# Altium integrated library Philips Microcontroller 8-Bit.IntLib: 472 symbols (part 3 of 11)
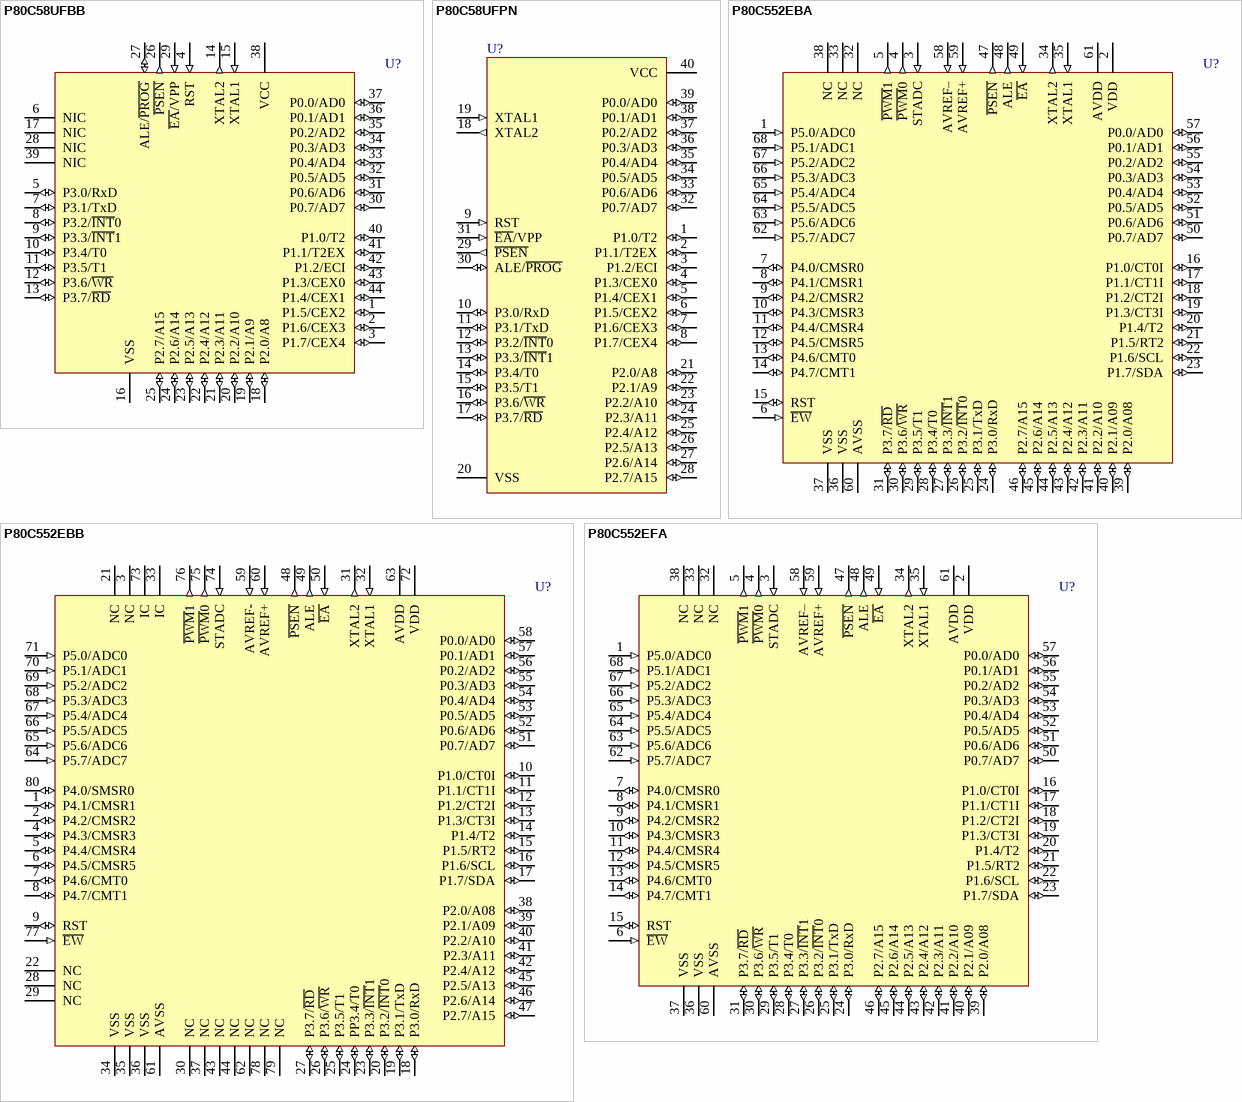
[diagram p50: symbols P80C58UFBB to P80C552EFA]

## P80C552EFA
designator U?
ROMless, Single-Chip 8-Bit Microcontroller with 10-bit A/D, Capture/Compare Timer, High-Speed Outputs, PWM
footprint SOT188-2_N (Leaded Chip Carrier, 68-Leads, Body 24.2x24.2mm, Pitch 1.27mm, IPC Medium Density)
footprint SOT188-2_L (Leaded Chip Carrier, 68-Leads, Body 24.2x24.2mm, Pitch 1.27mm, IPC High Density)
footprint SOT188-2_M (Leaded Chip Carrier, 68-Leads, Body 24.2x24.2mm, Pitch 1.27mm, IPC Low Density)
pins: 1 P5.0/ADC0 (in), 2 VDD (power), 3 STADC (in), 4 ~{PWM}0 (out), 5 ~{PWM}1 (out), 6 ~{EW} (in), 7 P4.0/CMSR0 (io), 8 P4.1/CMSR1 (io), 9 P4.2/CMSR2 (io), 10 P4.3/CMSR3 (io), 11 P4.4/CMSR4 (io), 12 P4.5/CMSR5 (io), 13 P4.6/CMT0 (io), 14 P4.7/CMT1 (io), 15 RST (io), 16 P1.0/CT0I (io), 17 P1.1/CT1I (io), 18 P1.2/CT2I (io), 19 P1.3/CT3I (io), 20 P1.4/T2 (io), 21 P1.5/RT2 (io), 22 P1.6/SCL (io), 23 P1.7/SDA (io), 24 P3.0/RxD (io), 25 P3.1/TxD (io), 26 P3.2/~{INT}0 (io), 27 P3.3/~{INT}1 (io), 28 P3.4/T0 (io), 29 P3.5/T1 (io), 30 P3.6/~{WR} (io), 31 P3.7/~{RD} (io), 32 NC, 33 NC, 34 XTAL2 (out), 35 XTAL1 (in), 36 VSS (power), 37 VSS (power), 38 NC, 39 P2.0/A08 (io), 40 P2.1/A09 (io), 41 P2.2/A10 (io), 42 P2.3/A11 (io), 43 P2.4/A12 (io), 44 P2.5/A13 (io), 45 P2.6/A14 (io), 46 P2.7/A15 (io), 47 ~{PSEN} (out), 48 ALE (out), 49 ~{EA} (in), 50 P0.7/AD7 (io), 51 P0.6/AD6 (io), 52 P0.5/AD5 (io), 53 P0.4/AD4 (io), 54 P0.3/AD3 (io), 55 P0.2/AD2 (io), 56 P0.1/AD1 (io), 57 P0.0/AD0 (io), 58 AVREF– (in), 59 AVREF+ (in), 60 AVSS (power), 61 AVDD (power), 62 P5.7/ADC7 (in), 63 P5.6/ADC6 (in), 64 P5.5/ADC5 (in), 65 P5.4/ADC4 (in), 66 P5.3/ADC3 (in), 67 P5.2/ADC2 (in), 68 P5.1/ADC1 (in)

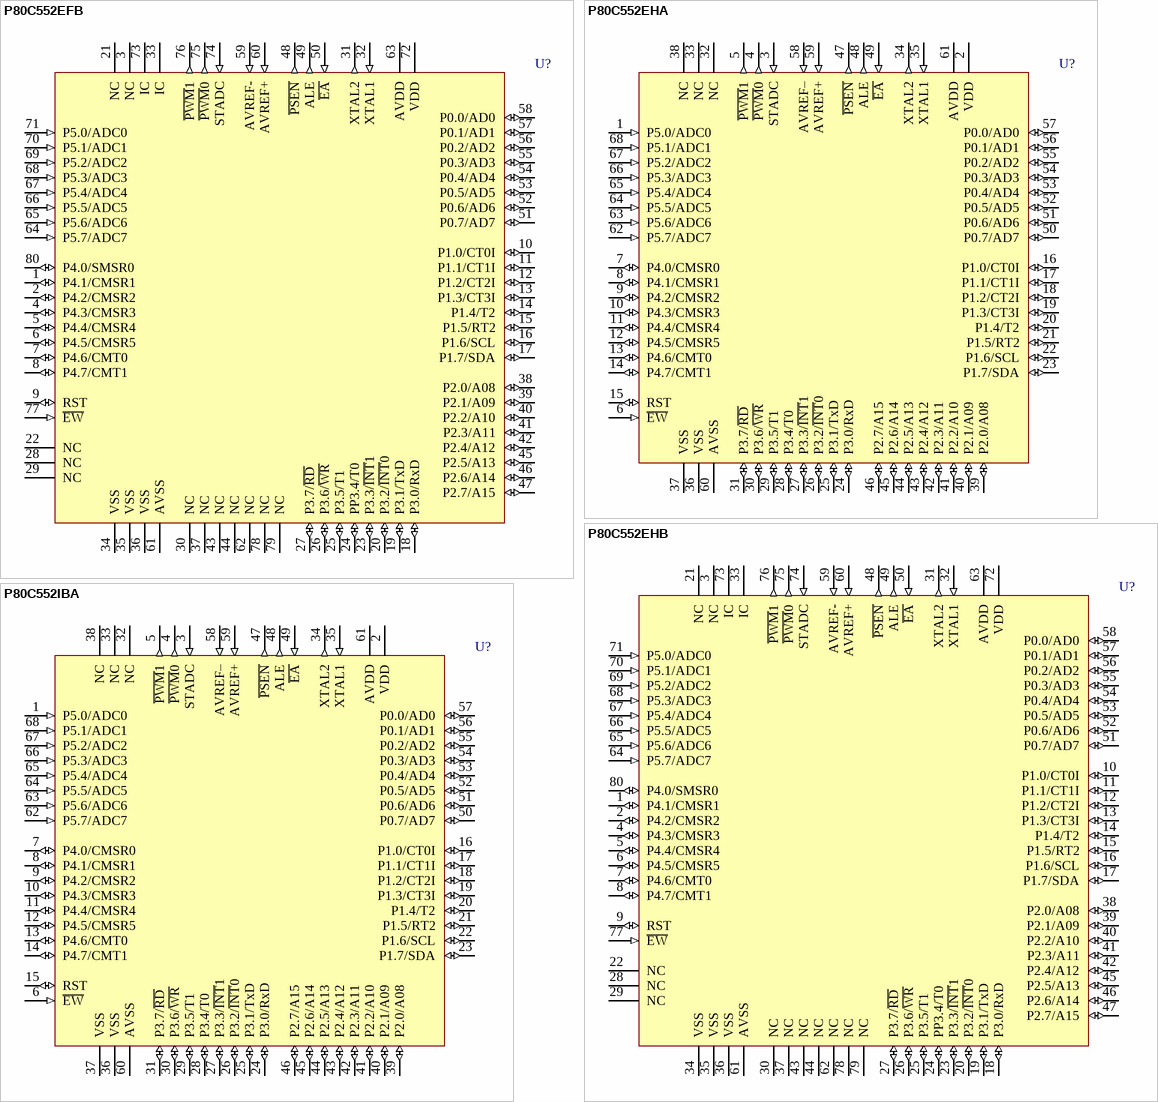
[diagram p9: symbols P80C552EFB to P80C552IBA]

## P80C552EFB
designator U?
ROMless, Single-Chip 8-Bit Microcontroller with 10-bit A/D, Capture/Compare Timer, High-Speed Outputs, PWM; DoNotConnect: Pins 33 & 73 are internally connected (IC), do not use.
footprint SOT318-2_N (QFP, 80-Leads, Body 20x14mm, Pitch 0.8mm, IPC Medium Density)
footprint SOT318-2_L (QFP, 80-Leads, Body 20x14mm, Pitch 0.8mm, IPC High Density)
footprint SOT318-2_M (QFP, 80-Leads, Body 20x14mm, Pitch 0.8mm, IPC Low Density)
pins: 1 P4.1/CMSR1 (io), 2 P4.2/CMSR2 (io), 3 NC, 4 P4.3/CMSR3 (io), 5 P4.4/CMSR4 (io), 6 P4.5/CMSR5 (io), 7 P4.6/CMT0 (io), 8 P4.7/CMT1 (io), 9 RST (io), 10 P1.0/CT0I (io), 11 P1.1/CT1I (io), 12 P1.2/CT2I (io), 13 P1.3/CT3I (io), 14 P1.4/T2 (io), 15 P1.5/RT2 (io), 16 P1.6/SCL (io), 17 P1.7/SDA (io), 18 P3.0/RxD (io), 19 P3.1/TxD (io), 20 P3.2/~{INT}0 (io), 21 NC, 22 NC, 23 P3.3/~{INT}1 (io), 24 PP3.4/T0 (io), 25 P3.5/T1 (io), 26 P3.6/~{WR} (io), 27 P3.7/~{RD} (io), 28 NC, 29 NC, 30 NC, 31 XTAL2 (out), 32 XTAL1 (in), 33 IC, 34 VSS (power), 35 VSS (power), 36 VSS (power), 37 NC, 38 P2.0/A08 (io), 39 P2.1/A09 (io), 40 P2.2/A10 (io), 41 P2.3/A11 (io), 42 P2.4/A12 (io), 43 NC, 44 NC, 45 P2.5/A13 (io), 46 P2.6/A14 (io), 47 P2.7/A15 (io), 48 ~{PSEN} (out), 49 ALE (out), 50 ~{EA} (in), 51 P0.7/AD7 (io), 52 P0.6/AD6 (io), 53 P0.5/AD5 (io), 54 P0.4/AD4 (io), 55 P0.3/AD3 (io), 56 P0.2/AD2 (io), 57 P0.1/AD1 (io), 58 P0.0/AD0 (io), 59 AVREF- (in), 60 AVREF+ (in), 61 AVSS (power), 62 NC, 63 AVDD (power), 64 P5.7/ADC7 (in), 65 P5.6/ADC6 (in), 66 P5.5/ADC5 (in), 67 P5.4/ADC4 (in), 68 P5.3/ADC3 (in), 69 P5.2/ADC2 (in), 70 P5.1/ADC1 (in), 71 P5.0/ADC0 (in), 72 VDD (power), 73 IC, 74 STADC (in), 75 ~{PWM}0 (out), 76 ~{PWM}1 (out), 77 ~{EW} (in), 78 NC, 79 NC, 80 P4.0/SMSR0 (io)

## P80C552EHA
designator U?
ROMless, Single-Chip 8-Bit Microcontroller with 10-bit A/D, Capture/Compare Timer, High-Speed Outputs, PWM
footprint SOT188-2_N (Leaded Chip Carrier, 68-Leads, Body 24.2x24.2mm, Pitch 1.27mm, IPC Medium Density)
footprint SOT188-2_L (Leaded Chip Carrier, 68-Leads, Body 24.2x24.2mm, Pitch 1.27mm, IPC High Density)
footprint SOT188-2_M (Leaded Chip Carrier, 68-Leads, Body 24.2x24.2mm, Pitch 1.27mm, IPC Low Density)
pins: 1 P5.0/ADC0 (in), 2 VDD (power), 3 STADC (in), 4 ~{PWM}0 (out), 5 ~{PWM}1 (out), 6 ~{EW} (in), 7 P4.0/CMSR0 (io), 8 P4.1/CMSR1 (io), 9 P4.2/CMSR2 (io), 10 P4.3/CMSR3 (io), 11 P4.4/CMSR4 (io), 12 P4.5/CMSR5 (io), 13 P4.6/CMT0 (io), 14 P4.7/CMT1 (io), 15 RST (io), 16 P1.0/CT0I (io), 17 P1.1/CT1I (io), 18 P1.2/CT2I (io), 19 P1.3/CT3I (io), 20 P1.4/T2 (io), 21 P1.5/RT2 (io), 22 P1.6/SCL (io), 23 P1.7/SDA (io), 24 P3.0/RxD (io), 25 P3.1/TxD (io), 26 P3.2/~{INT}0 (io), 27 P3.3/~{INT}1 (io), 28 P3.4/T0 (io), 29 P3.5/T1 (io), 30 P3.6/~{WR} (io), 31 P3.7/~{RD} (io), 32 NC, 33 NC, 34 XTAL2 (out), 35 XTAL1 (in), 36 VSS (power), 37 VSS (power), 38 NC, 39 P2.0/A08 (io), 40 P2.1/A09 (io), 41 P2.2/A10 (io), 42 P2.3/A11 (io), 43 P2.4/A12 (io), 44 P2.5/A13 (io), 45 P2.6/A14 (io), 46 P2.7/A15 (io), 47 ~{PSEN} (out), 48 ALE (out), 49 ~{EA} (in), 50 P0.7/AD7 (io), 51 P0.6/AD6 (io), 52 P0.5/AD5 (io), 53 P0.4/AD4 (io), 54 P0.3/AD3 (io), 55 P0.2/AD2 (io), 56 P0.1/AD1 (io), 57 P0.0/AD0 (io), 58 AVREF– (in), 59 AVREF+ (in), 60 AVSS (power), 61 AVDD (power), 62 P5.7/ADC7 (in), 63 P5.6/ADC6 (in), 64 P5.5/ADC5 (in), 65 P5.4/ADC4 (in), 66 P5.3/ADC3 (in), 67 P5.2/ADC2 (in), 68 P5.1/ADC1 (in)

## P80C552EHB
designator U?
ROMless, Single-Chip 8-Bit Microcontroller with 10-bit A/D, Capture/Compare Timer, High-Speed Outputs, PWM; DoNotConnect: Pins 33 & 73 are internally connected (IC), do not use.
footprint SOT318-2_N (QFP, 80-Leads, Body 20x14mm, Pitch 0.8mm, IPC Medium Density)
footprint SOT318-2_L (QFP, 80-Leads, Body 20x14mm, Pitch 0.8mm, IPC High Density)
footprint SOT318-2_M (QFP, 80-Leads, Body 20x14mm, Pitch 0.8mm, IPC Low Density)
pins: 1 P4.1/CMSR1 (io), 2 P4.2/CMSR2 (io), 3 NC, 4 P4.3/CMSR3 (io), 5 P4.4/CMSR4 (io), 6 P4.5/CMSR5 (io), 7 P4.6/CMT0 (io), 8 P4.7/CMT1 (io), 9 RST (io), 10 P1.0/CT0I (io), 11 P1.1/CT1I (io), 12 P1.2/CT2I (io), 13 P1.3/CT3I (io), 14 P1.4/T2 (io), 15 P1.5/RT2 (io), 16 P1.6/SCL (io), 17 P1.7/SDA (io), 18 P3.0/RxD (io), 19 P3.1/TxD (io), 20 P3.2/~{INT}0 (io), 21 NC, 22 NC, 23 P3.3/~{INT}1 (io), 24 PP3.4/T0 (io), 25 P3.5/T1 (io), 26 P3.6/~{WR} (io), 27 P3.7/~{RD} (io), 28 NC, 29 NC, 30 NC, 31 XTAL2 (out), 32 XTAL1 (in), 33 IC, 34 VSS (power), 35 VSS (power), 36 VSS (power), 37 NC, 38 P2.0/A08 (io), 39 P2.1/A09 (io), 40 P2.2/A10 (io), 41 P2.3/A11 (io), 42 P2.4/A12 (io), 43 NC, 44 NC, 45 P2.5/A13 (io), 46 P2.6/A14 (io), 47 P2.7/A15 (io), 48 ~{PSEN} (out), 49 ALE (out), 50 ~{EA} (in), 51 P0.7/AD7 (io), 52 P0.6/AD6 (io), 53 P0.5/AD5 (io), 54 P0.4/AD4 (io), 55 P0.3/AD3 (io), 56 P0.2/AD2 (io), 57 P0.1/AD1 (io), 58 P0.0/AD0 (io), 59 AVREF- (in), 60 AVREF+ (in), 61 AVSS (power), 62 NC, 63 AVDD (power), 64 P5.7/ADC7 (in), 65 P5.6/ADC6 (in), 66 P5.5/ADC5 (in), 67 P5.4/ADC4 (in), 68 P5.3/ADC3 (in), 69 P5.2/ADC2 (in), 70 P5.1/ADC1 (in), 71 P5.0/ADC0 (in), 72 VDD (power), 73 IC, 74 STADC (in), 75 ~{PWM}0 (out), 76 ~{PWM}1 (out), 77 ~{EW} (in), 78 NC, 79 NC, 80 P4.0/SMSR0 (io)

## P80C552IBA
designator U?
ROMless, Single-Chip 8-Bit Microcontroller with 10-bit A/D, Capture/Compare Timer, High-Speed Outputs, PWM
footprint SOT188-2_N (Leaded Chip Carrier, 68-Leads, Body 24.2x24.2mm, Pitch 1.27mm, IPC Medium Density)
footprint SOT188-2_L (Leaded Chip Carrier, 68-Leads, Body 24.2x24.2mm, Pitch 1.27mm, IPC High Density)
footprint SOT188-2_M (Leaded Chip Carrier, 68-Leads, Body 24.2x24.2mm, Pitch 1.27mm, IPC Low Density)
pins: 1 P5.0/ADC0 (in), 2 VDD (power), 3 STADC (in), 4 ~{PWM}0 (out), 5 ~{PWM}1 (out), 6 ~{EW} (in), 7 P4.0/CMSR0 (io), 8 P4.1/CMSR1 (io), 9 P4.2/CMSR2 (io), 10 P4.3/CMSR3 (io), 11 P4.4/CMSR4 (io), 12 P4.5/CMSR5 (io), 13 P4.6/CMT0 (io), 14 P4.7/CMT1 (io), 15 RST (io), 16 P1.0/CT0I (io), 17 P1.1/CT1I (io), 18 P1.2/CT2I (io), 19 P1.3/CT3I (io), 20 P1.4/T2 (io), 21 P1.5/RT2 (io), 22 P1.6/SCL (io), 23 P1.7/SDA (io), 24 P3.0/RxD (io), 25 P3.1/TxD (io), 26 P3.2/~{INT}0 (io), 27 P3.3/~{INT}1 (io), 28 P3.4/T0 (io), 29 P3.5/T1 (io), 30 P3.6/~{WR} (io), 31 P3.7/~{RD} (io), 32 NC, 33 NC, 34 XTAL2 (out), 35 XTAL1 (in), 36 VSS (power), 37 VSS (power), 38 NC, 39 P2.0/A08 (io), 40 P2.1/A09 (io), 41 P2.2/A10 (io), 42 P2.3/A11 (io), 43 P2.4/A12 (io), 44 P2.5/A13 (io), 45 P2.6/A14 (io), 46 P2.7/A15 (io), 47 ~{PSEN} (out), 48 ALE (out), 49 ~{EA} (in), 50 P0.7/AD7 (io), 51 P0.6/AD6 (io), 52 P0.5/AD5 (io), 53 P0.4/AD4 (io), 54 P0.3/AD3 (io), 55 P0.2/AD2 (io), 56 P0.1/AD1 (io), 57 P0.0/AD0 (io), 58 AVREF– (in), 59 AVREF+ (in), 60 AVSS (power), 61 AVDD (power), 62 P5.7/ADC7 (in), 63 P5.6/ADC6 (in), 64 P5.5/ADC5 (in), 65 P5.4/ADC4 (in), 66 P5.3/ADC3 (in), 67 P5.2/ADC2 (in), 68 P5.1/ADC1 (in)

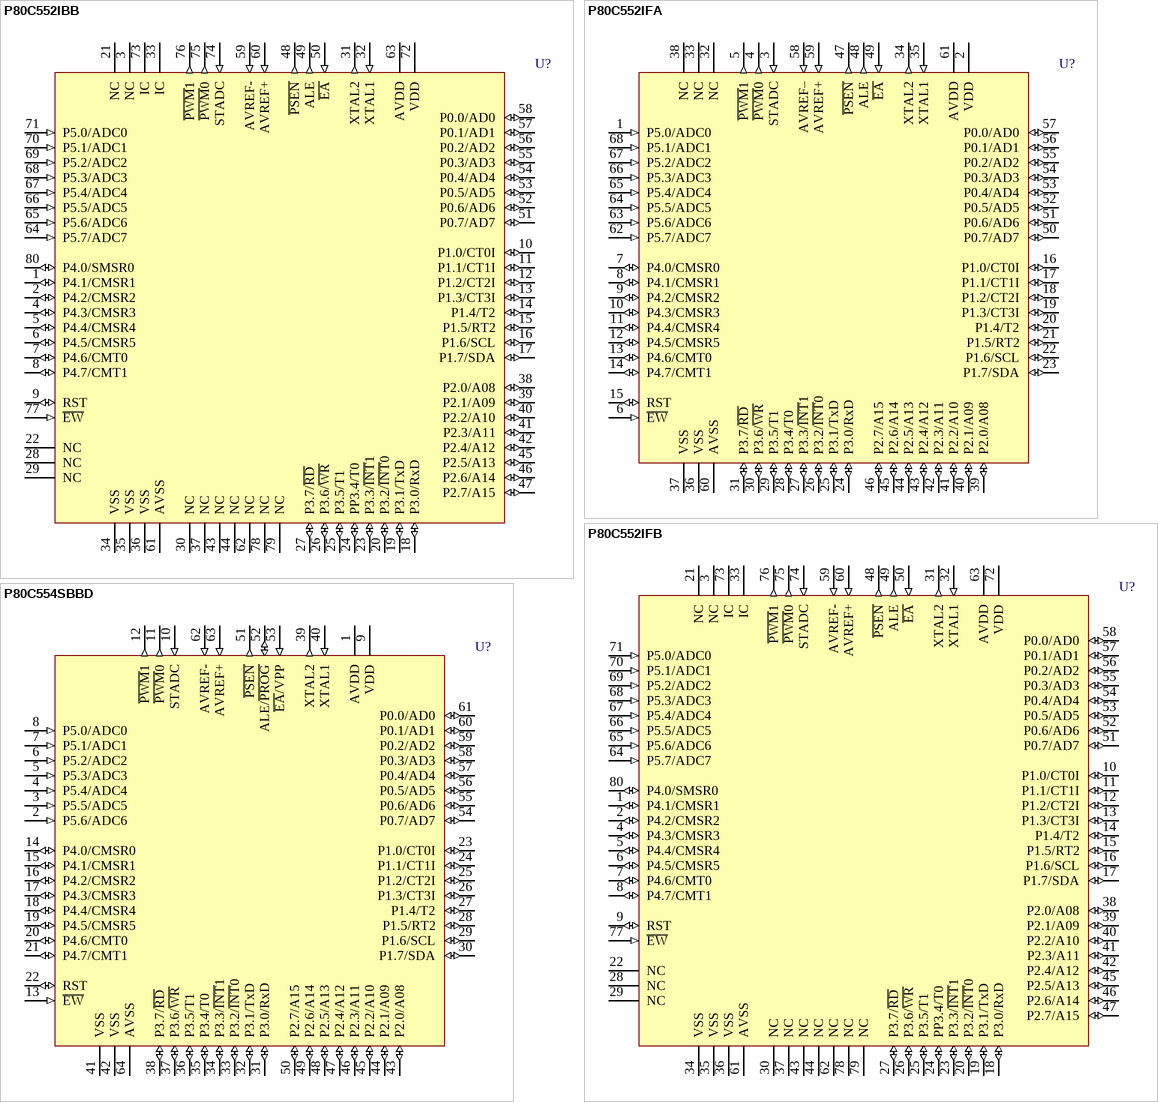
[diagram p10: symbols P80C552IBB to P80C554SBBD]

## P80C552IBB
designator U?
ROMless, Single-Chip 8-Bit Microcontroller with 10-bit A/D, Capture/Compare Timer, High-Speed Outputs, PWM; DoNotConnect: Pins 33 & 73 are internally connected (IC), do not use.
footprint SOT318-2_N (QFP, 80-Leads, Body 20x14mm, Pitch 0.8mm, IPC Medium Density)
footprint SOT318-2_L (QFP, 80-Leads, Body 20x14mm, Pitch 0.8mm, IPC High Density)
footprint SOT318-2_M (QFP, 80-Leads, Body 20x14mm, Pitch 0.8mm, IPC Low Density)
pins: 1 P4.1/CMSR1 (io), 2 P4.2/CMSR2 (io), 3 NC, 4 P4.3/CMSR3 (io), 5 P4.4/CMSR4 (io), 6 P4.5/CMSR5 (io), 7 P4.6/CMT0 (io), 8 P4.7/CMT1 (io), 9 RST (io), 10 P1.0/CT0I (io), 11 P1.1/CT1I (io), 12 P1.2/CT2I (io), 13 P1.3/CT3I (io), 14 P1.4/T2 (io), 15 P1.5/RT2 (io), 16 P1.6/SCL (io), 17 P1.7/SDA (io), 18 P3.0/RxD (io), 19 P3.1/TxD (io), 20 P3.2/~{INT}0 (io), 21 NC, 22 NC, 23 P3.3/~{INT}1 (io), 24 PP3.4/T0 (io), 25 P3.5/T1 (io), 26 P3.6/~{WR} (io), 27 P3.7/~{RD} (io), 28 NC, 29 NC, 30 NC, 31 XTAL2 (out), 32 XTAL1 (in), 33 IC, 34 VSS (power), 35 VSS (power), 36 VSS (power), 37 NC, 38 P2.0/A08 (io), 39 P2.1/A09 (io), 40 P2.2/A10 (io), 41 P2.3/A11 (io), 42 P2.4/A12 (io), 43 NC, 44 NC, 45 P2.5/A13 (io), 46 P2.6/A14 (io), 47 P2.7/A15 (io), 48 ~{PSEN} (out), 49 ALE (out), 50 ~{EA} (in), 51 P0.7/AD7 (io), 52 P0.6/AD6 (io), 53 P0.5/AD5 (io), 54 P0.4/AD4 (io), 55 P0.3/AD3 (io), 56 P0.2/AD2 (io), 57 P0.1/AD1 (io), 58 P0.0/AD0 (io), 59 AVREF- (in), 60 AVREF+ (in), 61 AVSS (power), 62 NC, 63 AVDD (power), 64 P5.7/ADC7 (in), 65 P5.6/ADC6 (in), 66 P5.5/ADC5 (in), 67 P5.4/ADC4 (in), 68 P5.3/ADC3 (in), 69 P5.2/ADC2 (in), 70 P5.1/ADC1 (in), 71 P5.0/ADC0 (in), 72 VDD (power), 73 IC, 74 STADC (in), 75 ~{PWM}0 (out), 76 ~{PWM}1 (out), 77 ~{EW} (in), 78 NC, 79 NC, 80 P4.0/SMSR0 (io)

## P80C552IFA
designator U?
ROMless, Single-Chip 8-Bit Microcontroller with 10-bit A/D, Capture/Compare Timer, High-Speed Outputs, PWM
footprint SOT188-2_N (Leaded Chip Carrier, 68-Leads, Body 24.2x24.2mm, Pitch 1.27mm, IPC Medium Density)
footprint SOT188-2_L (Leaded Chip Carrier, 68-Leads, Body 24.2x24.2mm, Pitch 1.27mm, IPC High Density)
footprint SOT188-2_M (Leaded Chip Carrier, 68-Leads, Body 24.2x24.2mm, Pitch 1.27mm, IPC Low Density)
pins: 1 P5.0/ADC0 (in), 2 VDD (power), 3 STADC (in), 4 ~{PWM}0 (out), 5 ~{PWM}1 (out), 6 ~{EW} (in), 7 P4.0/CMSR0 (io), 8 P4.1/CMSR1 (io), 9 P4.2/CMSR2 (io), 10 P4.3/CMSR3 (io), 11 P4.4/CMSR4 (io), 12 P4.5/CMSR5 (io), 13 P4.6/CMT0 (io), 14 P4.7/CMT1 (io), 15 RST (io), 16 P1.0/CT0I (io), 17 P1.1/CT1I (io), 18 P1.2/CT2I (io), 19 P1.3/CT3I (io), 20 P1.4/T2 (io), 21 P1.5/RT2 (io), 22 P1.6/SCL (io), 23 P1.7/SDA (io), 24 P3.0/RxD (io), 25 P3.1/TxD (io), 26 P3.2/~{INT}0 (io), 27 P3.3/~{INT}1 (io), 28 P3.4/T0 (io), 29 P3.5/T1 (io), 30 P3.6/~{WR} (io), 31 P3.7/~{RD} (io), 32 NC, 33 NC, 34 XTAL2 (out), 35 XTAL1 (in), 36 VSS (power), 37 VSS (power), 38 NC, 39 P2.0/A08 (io), 40 P2.1/A09 (io), 41 P2.2/A10 (io), 42 P2.3/A11 (io), 43 P2.4/A12 (io), 44 P2.5/A13 (io), 45 P2.6/A14 (io), 46 P2.7/A15 (io), 47 ~{PSEN} (out), 48 ALE (out), 49 ~{EA} (in), 50 P0.7/AD7 (io), 51 P0.6/AD6 (io), 52 P0.5/AD5 (io), 53 P0.4/AD4 (io), 54 P0.3/AD3 (io), 55 P0.2/AD2 (io), 56 P0.1/AD1 (io), 57 P0.0/AD0 (io), 58 AVREF– (in), 59 AVREF+ (in), 60 AVSS (power), 61 AVDD (power), 62 P5.7/ADC7 (in), 63 P5.6/ADC6 (in), 64 P5.5/ADC5 (in), 65 P5.4/ADC4 (in), 66 P5.3/ADC3 (in), 67 P5.2/ADC2 (in), 68 P5.1/ADC1 (in)

## P80C552IFB
designator U?
ROMless, Single-Chip 8-Bit Microcontroller with 10-bit A/D, Capture/Compare Timer, High-Speed Outputs, PWM; DoNotConnect: Pins 33 & 73 are internally connected (IC), do not use.
footprint SOT318-2_N (QFP, 80-Leads, Body 20x14mm, Pitch 0.8mm, IPC Medium Density)
footprint SOT318-2_L (QFP, 80-Leads, Body 20x14mm, Pitch 0.8mm, IPC High Density)
footprint SOT318-2_M (QFP, 80-Leads, Body 20x14mm, Pitch 0.8mm, IPC Low Density)
pins: 1 P4.1/CMSR1 (io), 2 P4.2/CMSR2 (io), 3 NC, 4 P4.3/CMSR3 (io), 5 P4.4/CMSR4 (io), 6 P4.5/CMSR5 (io), 7 P4.6/CMT0 (io), 8 P4.7/CMT1 (io), 9 RST (io), 10 P1.0/CT0I (io), 11 P1.1/CT1I (io), 12 P1.2/CT2I (io), 13 P1.3/CT3I (io), 14 P1.4/T2 (io), 15 P1.5/RT2 (io), 16 P1.6/SCL (io), 17 P1.7/SDA (io), 18 P3.0/RxD (io), 19 P3.1/TxD (io), 20 P3.2/~{INT}0 (io), 21 NC, 22 NC, 23 P3.3/~{INT}1 (io), 24 PP3.4/T0 (io), 25 P3.5/T1 (io), 26 P3.6/~{WR} (io), 27 P3.7/~{RD} (io), 28 NC, 29 NC, 30 NC, 31 XTAL2 (out), 32 XTAL1 (in), 33 IC, 34 VSS (power), 35 VSS (power), 36 VSS (power), 37 NC, 38 P2.0/A08 (io), 39 P2.1/A09 (io), 40 P2.2/A10 (io), 41 P2.3/A11 (io), 42 P2.4/A12 (io), 43 NC, 44 NC, 45 P2.5/A13 (io), 46 P2.6/A14 (io), 47 P2.7/A15 (io), 48 ~{PSEN} (out), 49 ALE (out), 50 ~{EA} (in), 51 P0.7/AD7 (io), 52 P0.6/AD6 (io), 53 P0.5/AD5 (io), 54 P0.4/AD4 (io), 55 P0.3/AD3 (io), 56 P0.2/AD2 (io), 57 P0.1/AD1 (io), 58 P0.0/AD0 (io), 59 AVREF- (in), 60 AVREF+ (in), 61 AVSS (power), 62 NC, 63 AVDD (power), 64 P5.7/ADC7 (in), 65 P5.6/ADC6 (in), 66 P5.5/ADC5 (in), 67 P5.4/ADC4 (in), 68 P5.3/ADC3 (in), 69 P5.2/ADC2 (in), 70 P5.1/ADC1 (in), 71 P5.0/ADC0 (in), 72 VDD (power), 73 IC, 74 STADC (in), 75 ~{PWM}0 (out), 76 ~{PWM}1 (out), 77 ~{EW} (in), 78 NC, 79 NC, 80 P4.0/SMSR0 (io)

## P80C554SBBD
designator U?
80C51 8-Bit Microcontroller - 6-Clock Operation, 16K/512 ROMless, 7-channel 10-bit A/D, I²C, PWM, Capture/Compare, High I/O
footprint SOT314-2_N (Thin QFP, 64-Leads, Body 10x10mm, Pitch 0.5mm, IPC Medium Density)
footprint SOT314-2_L (Thin QFP, 64-Leads, Body 10x10mm, Pitch 0.5mm, IPC High Density)
footprint SOT314-2_M (Thin QFP, 64-Leads, Body 10x10mm, Pitch 0.5mm, IPC Low Density)
pins: 1 AVDD (power), 2 P5.6/ADC6 (in), 3 P5.5/ADC5 (in), 4 P5.4/ADC4 (in), 5 P5.3/ADC3 (in), 6 P5.2/ADC2 (in), 7 P5.1/ADC1 (in), 8 P5.0/ADC0 (in), 9 VDD (power), 10 STADC (in), 11 ~{PWM}0 (out), 12 ~{PWM}1 (out), 13 ~{EW} (in), 14 P4.0/CMSR0 (io), 15 P4.1/CMSR1 (io), 16 P4.2/CMSR2 (io), 17 P4.3/CMSR3 (io), 18 P4.4/CMSR4 (io), 19 P4.5/CMSR5 (io), 20 P4.6/CMT0 (io), 21 P4.7/CMT1 (io), 22 RST (io), 23 P1.0/CT0I (io), 24 P1.1/CT1I (io), 25 P1.2/CT2I (io), 26 P1.3/CT3I (io), 27 P1.4/T2 (io), 28 P1.5/RT2 (io), 29 P1.6/SCL (io), 30 P1.7/SDA (io), 31 P3.0/RxD (io), 32 P3.1/TxD (io), 33 P3.2/~{INT}0 (io), 34 P3.3/~{INT}1 (io), 35 P3.4/T0 (io), 36 P3.5/T1 (io), 37 P3.6/~{WR} (io), 38 P3.7/~{RD} (io), 39 XTAL2 (out), 40 XTAL1 (in), 41 VSS (power), 42 VSS (power), 43 P2.0/A08 (io), 44 P2.1/A09 (io), 45 P2.2/A10 (io), 46 P2.3/A11 (io), 47 P2.4/A12 (io), 48 P2.5/A13 (io), 49 P2.6/A14 (io), 50 P2.7/A15 (io), 51 ~{PSEN} (out), 52 ALE/~{PROG} (io), 53 ~{EA}/VPP (in), 54 P0.7/AD7 (io), 55 P0.6/AD6 (io), 56 P0.5/AD5 (io), 57 P0.4/AD4 (io), 58 P0.3/AD3 (io), 59 P0.2/AD2 (io), 60 P0.1/AD1 (io), 61 P0.0/AD0 (io), 62 AVREF- (in), 63 AVREF+ (in), 64 AVSS (power)

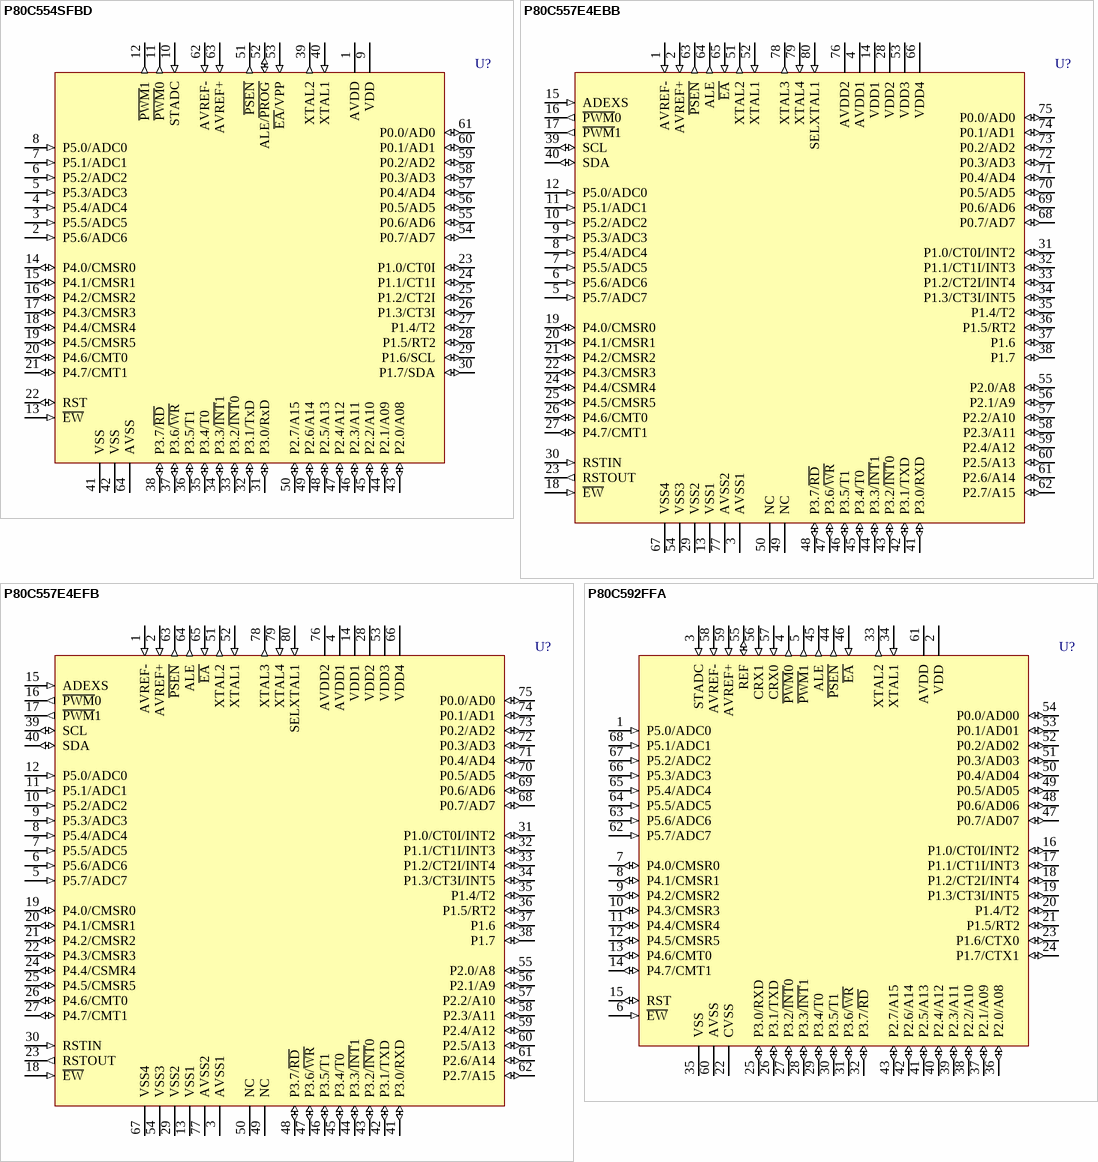
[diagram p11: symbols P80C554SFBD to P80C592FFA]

## P80C554SFBD
designator U?
80C51 8-Bit Microcontroller - 6-Clock Operation, 16K/512 ROMless, 7-channel 10-bit A/D, I²C, PWM, Capture/Compare, High I/O
footprint SOT314-2_N (Thin QFP, 64-Leads, Body 10x10mm, Pitch 0.5mm, IPC Medium Density)
footprint SOT314-2_L (Thin QFP, 64-Leads, Body 10x10mm, Pitch 0.5mm, IPC High Density)
footprint SOT314-2_M (Thin QFP, 64-Leads, Body 10x10mm, Pitch 0.5mm, IPC Low Density)
pins: 1 AVDD (power), 2 P5.6/ADC6 (in), 3 P5.5/ADC5 (in), 4 P5.4/ADC4 (in), 5 P5.3/ADC3 (in), 6 P5.2/ADC2 (in), 7 P5.1/ADC1 (in), 8 P5.0/ADC0 (in), 9 VDD (power), 10 STADC (in), 11 ~{PWM}0 (out), 12 ~{PWM}1 (out), 13 ~{EW} (in), 14 P4.0/CMSR0 (io), 15 P4.1/CMSR1 (io), 16 P4.2/CMSR2 (io), 17 P4.3/CMSR3 (io), 18 P4.4/CMSR4 (io), 19 P4.5/CMSR5 (io), 20 P4.6/CMT0 (io), 21 P4.7/CMT1 (io), 22 RST (io), 23 P1.0/CT0I (io), 24 P1.1/CT1I (io), 25 P1.2/CT2I (io), 26 P1.3/CT3I (io), 27 P1.4/T2 (io), 28 P1.5/RT2 (io), 29 P1.6/SCL (io), 30 P1.7/SDA (io), 31 P3.0/RxD (io), 32 P3.1/TxD (io), 33 P3.2/~{INT}0 (io), 34 P3.3/~{INT}1 (io), 35 P3.4/T0 (io), 36 P3.5/T1 (io), 37 P3.6/~{WR} (io), 38 P3.7/~{RD} (io), 39 XTAL2 (out), 40 XTAL1 (in), 41 VSS (power), 42 VSS (power), 43 P2.0/A08 (io), 44 P2.1/A09 (io), 45 P2.2/A10 (io), 46 P2.3/A11 (io), 47 P2.4/A12 (io), 48 P2.5/A13 (io), 49 P2.6/A14 (io), 50 P2.7/A15 (io), 51 ~{PSEN} (out), 52 ALE/~{PROG} (io), 53 ~{EA}/VPP (in), 54 P0.7/AD7 (io), 55 P0.6/AD6 (io), 56 P0.5/AD5 (io), 57 P0.4/AD4 (io), 58 P0.3/AD3 (io), 59 P0.2/AD2 (io), 60 P0.1/AD1 (io), 61 P0.0/AD0 (io), 62 AVREF- (in), 63 AVREF+ (in), 64 AVSS (power)

## P80C557E4EBB
designator U?
Single-Chip 8-Bit Microcontroller, ROMless Type
footprint SOT318-1_N (QFP, 80-Leads, Body 20x14mm, Pitch 0.8mm, IPC Medium Density)
footprint SOT318-1_L (QFP, 80-Leads, Body 20x14mm, Pitch 0.8mm, IPC High Density)
footprint SOT318-1_M (QFP, 80-Leads, Body 20x14mm, Pitch 0.8mm, IPC Low Density)
pins: 1 AVREF- (in), 2 AVREF+ (in), 3 AVSS1 (power), 4 AVDD1 (power), 5 P5.7/ADC7 (in), 6 P5.6/ADC6 (in), 7 P5.5/ADC5 (in), 8 P5.4/ADC4 (in), 9 P5.3/ADC3 (in), 10 P5.2/ADC2 (in), 11 P5.1/ADC1 (in), 12 P5.0/ADC0 (in), 13 VSS1 (power), 14 VDD1 (power), 15 ADEXS (in), 16 ~{PWM}0 (out), 17 ~{PWM}1 (out), 18 ~{EW} (in), 19 P4.0/CMSR0 (io), 20 P4.1/CMSR1 (io), 21 P4.2/CMSR2 (io), 22 P4.3/CMSR3 (io), 23 RSTOUT (out), 24 P4.4/CSMR4 (io), 25 P4.5/CMSR5 (io), 26 P4.6/CMT0 (io), 27 P4.7/CMT1 (io), 28 VDD2 (power), 29 VSS2 (power), 30 RSTIN (in), 31 P1.0/CT0I/INT2 (io), 32 P1.1/CT1I/INT3 (io), 33 P1.2/CT2I/INT4 (io), 34 P1.3/CT3I/INT5 (io), 35 P1.4/T2 (io), 36 P1.5/RT2 (io), 37 P1.6 (io), 38 P1.7 (io), 39 SCL (io), 40 SDA (io), 41 P3.0/RXD (io), 42 P3.1/TXD (io), 43 P3.2/~{INT}0 (io), 44 P3.3/~{INT}1 (io), 45 P3.4/T0 (io), 46 P3.5/T1 (io), 47 P3.6/~{WR} (io), 48 P3.7/~{RD} (io), 49 NC, 50 NC, 51 XTAL2 (out), 52 XTAL1 (in), 53 VDD3 (power), 54 VSS3 (power), 55 P2.0/A8 (io), 56 P2.1/A9 (io), 57 P2.2/A10 (io), 58 P2.3/A11 (io), 59 P2.4/A12 (io), 60 P2.5/A13 (io), 61 P2.6/A14 (io), 62 P2.7/A15 (io), 63 ~{PSEN} (out), 64 ALE (out), 65 ~{EA} (in), 66 VDD4 (power), 67 VSS4 (power), 68 P0.7/AD7 (io), 69 P0.6/AD6 (io), 70 P0.5/AD5 (io), 71 P0.4/AD4 (io), 72 P0.3/AD3 (io), 73 P0.2/AD2 (io), 74 P0.1/AD1 (io), 75 P0.0/AD0 (io), 76 AVDD2 (power), 77 AVSS2 (power), 78 XTAL3 (out), 79 XTAL4 (in), 80 SELXTAL1 (in)

## P80C557E4EFB
designator U?
Single-Chip 8-Bit Microcontroller, ROMless Type
footprint SOT318-1_N (QFP, 80-Leads, Body 20x14mm, Pitch 0.8mm, IPC Medium Density)
footprint SOT318-1_L (QFP, 80-Leads, Body 20x14mm, Pitch 0.8mm, IPC High Density)
footprint SOT318-1_M (QFP, 80-Leads, Body 20x14mm, Pitch 0.8mm, IPC Low Density)
pins: 1 AVREF- (in), 2 AVREF+ (in), 3 AVSS1 (power), 4 AVDD1 (power), 5 P5.7/ADC7 (in), 6 P5.6/ADC6 (in), 7 P5.5/ADC5 (in), 8 P5.4/ADC4 (in), 9 P5.3/ADC3 (in), 10 P5.2/ADC2 (in), 11 P5.1/ADC1 (in), 12 P5.0/ADC0 (in), 13 VSS1 (power), 14 VDD1 (power), 15 ADEXS (in), 16 ~{PWM}0 (out), 17 ~{PWM}1 (out), 18 ~{EW} (in), 19 P4.0/CMSR0 (io), 20 P4.1/CMSR1 (io), 21 P4.2/CMSR2 (io), 22 P4.3/CMSR3 (io), 23 RSTOUT (out), 24 P4.4/CSMR4 (io), 25 P4.5/CMSR5 (io), 26 P4.6/CMT0 (io), 27 P4.7/CMT1 (io), 28 VDD2 (power), 29 VSS2 (power), 30 RSTIN (in), 31 P1.0/CT0I/INT2 (io), 32 P1.1/CT1I/INT3 (io), 33 P1.2/CT2I/INT4 (io), 34 P1.3/CT3I/INT5 (io), 35 P1.4/T2 (io), 36 P1.5/RT2 (io), 37 P1.6 (io), 38 P1.7 (io), 39 SCL (io), 40 SDA (io), 41 P3.0/RXD (io), 42 P3.1/TXD (io), 43 P3.2/~{INT}0 (io), 44 P3.3/~{INT}1 (io), 45 P3.4/T0 (io), 46 P3.5/T1 (io), 47 P3.6/~{WR} (io), 48 P3.7/~{RD} (io), 49 NC, 50 NC, 51 XTAL2 (out), 52 XTAL1 (in), 53 VDD3 (power), 54 VSS3 (power), 55 P2.0/A8 (io), 56 P2.1/A9 (io), 57 P2.2/A10 (io), 58 P2.3/A11 (io), 59 P2.4/A12 (io), 60 P2.5/A13 (io), 61 P2.6/A14 (io), 62 P2.7/A15 (io), 63 ~{PSEN} (out), 64 ALE (out), 65 ~{EA} (in), 66 VDD4 (power), 67 VSS4 (power), 68 P0.7/AD7 (io), 69 P0.6/AD6 (io), 70 P0.5/AD5 (io), 71 P0.4/AD4 (io), 72 P0.3/AD3 (io), 73 P0.2/AD2 (io), 74 P0.1/AD1 (io), 75 P0.0/AD0 (io), 76 AVDD2 (power), 77 AVSS2 (power), 78 XTAL3 (out), 79 XTAL4 (in), 80 SELXTAL1 (in)

## P80C592FFA
designator U?
8-Bit Microcontroller with On-Chip CAN, ROMless
footprint SOT188-2_N (Leaded Chip Carrier, 68-Leads, Body 24.2x24.2mm, Pitch 1.27mm, IPC Medium Density)
footprint SOT188-2_L (Leaded Chip Carrier, 68-Leads, Body 24.2x24.2mm, Pitch 1.27mm, IPC High Density)
footprint SOT188-2_M (Leaded Chip Carrier, 68-Leads, Body 24.2x24.2mm, Pitch 1.27mm, IPC Low Density)
pins: 1 P5.0/ADC0 (in), 2 VDD (power), 3 STADC (in), 4 ~{PWM}0 (out), 5 ~{PWM}1 (out), 6 ~{EW} (in), 7 P4.0/CMSR0 (io), 8 P4.1/CMSR1 (io), 9 P4.2/CMSR2 (io), 10 P4.3/CMSR3 (io), 11 P4.4/CMSR4 (io), 12 P4.5/CMSR5 (io), 13 P4.6/CMT0 (io), 14 P4.7/CMT1 (io), 15 RST (io), 16 P1.0/CT0I/INT2 (io), 17 P1.1/CT1I/INT3 (io), 18 P1.2/CT2I/INT4 (io), 19 P1.3/CT3I/INT5 (io), 20 P1.4/T2 (io), 21 P1.5/RT2 (io), 22 CVSS (power), 23 P1.6/CTX0 (io), 24 P1.7/CTX1 (io), 25 P3.0/RXD (io), 26 P3.1/TXD (io), 27 P3.2/~{INT}0 (io), 28 P3.3/~{INT}1 (io), 29 P3.4/T0 (io), 30 P3.5/T1 (io), 31 P3.6/~{WR} (io), 32 P3.7/~{RD} (io), 33 XTAL2 (out), 34 XTAL1 (in), 35 VSS (power), 36 P2.0/A08 (io), 37 P2.1/A09 (io), 38 P2.2/A10 (io), 39 P2.3/A11 (io), 40 P2.4/A12 (io), 41 P2.5/A13 (io), 42 P2.6/A14 (io), 43 P2.7/A15 (io), 44 ~{PSEN} (out), 45 ALE (out), 46 ~{EA} (in), 47 P0.7/AD07 (io), 48 P0.6/AD06 (io), 49 P0.5/AD05 (io), 50 P0.4/AD04 (io), 51 P0.3/AD03 (io), 52 P0.2/AD02 (io), 53 P0.1/AD01 (io), 54 P0.0/AD00 (io), 55 REF (io), 56 CRX1 (in), 57 CRX0 (in), 58 AVREF- (in), 59 AVREF+ (in), 60 AVSS (power), 61 AVDD (power), 62 P5.7/ADC7 (in), 63 P5.6/ADC6 (in), 64 P5.5/ADC5 (in), 65 P5.4/ADC4 (in), 66 P5.3/ADC3 (in), 67 P5.2/ADC2 (in), 68 P5.1/ADC1 (in)

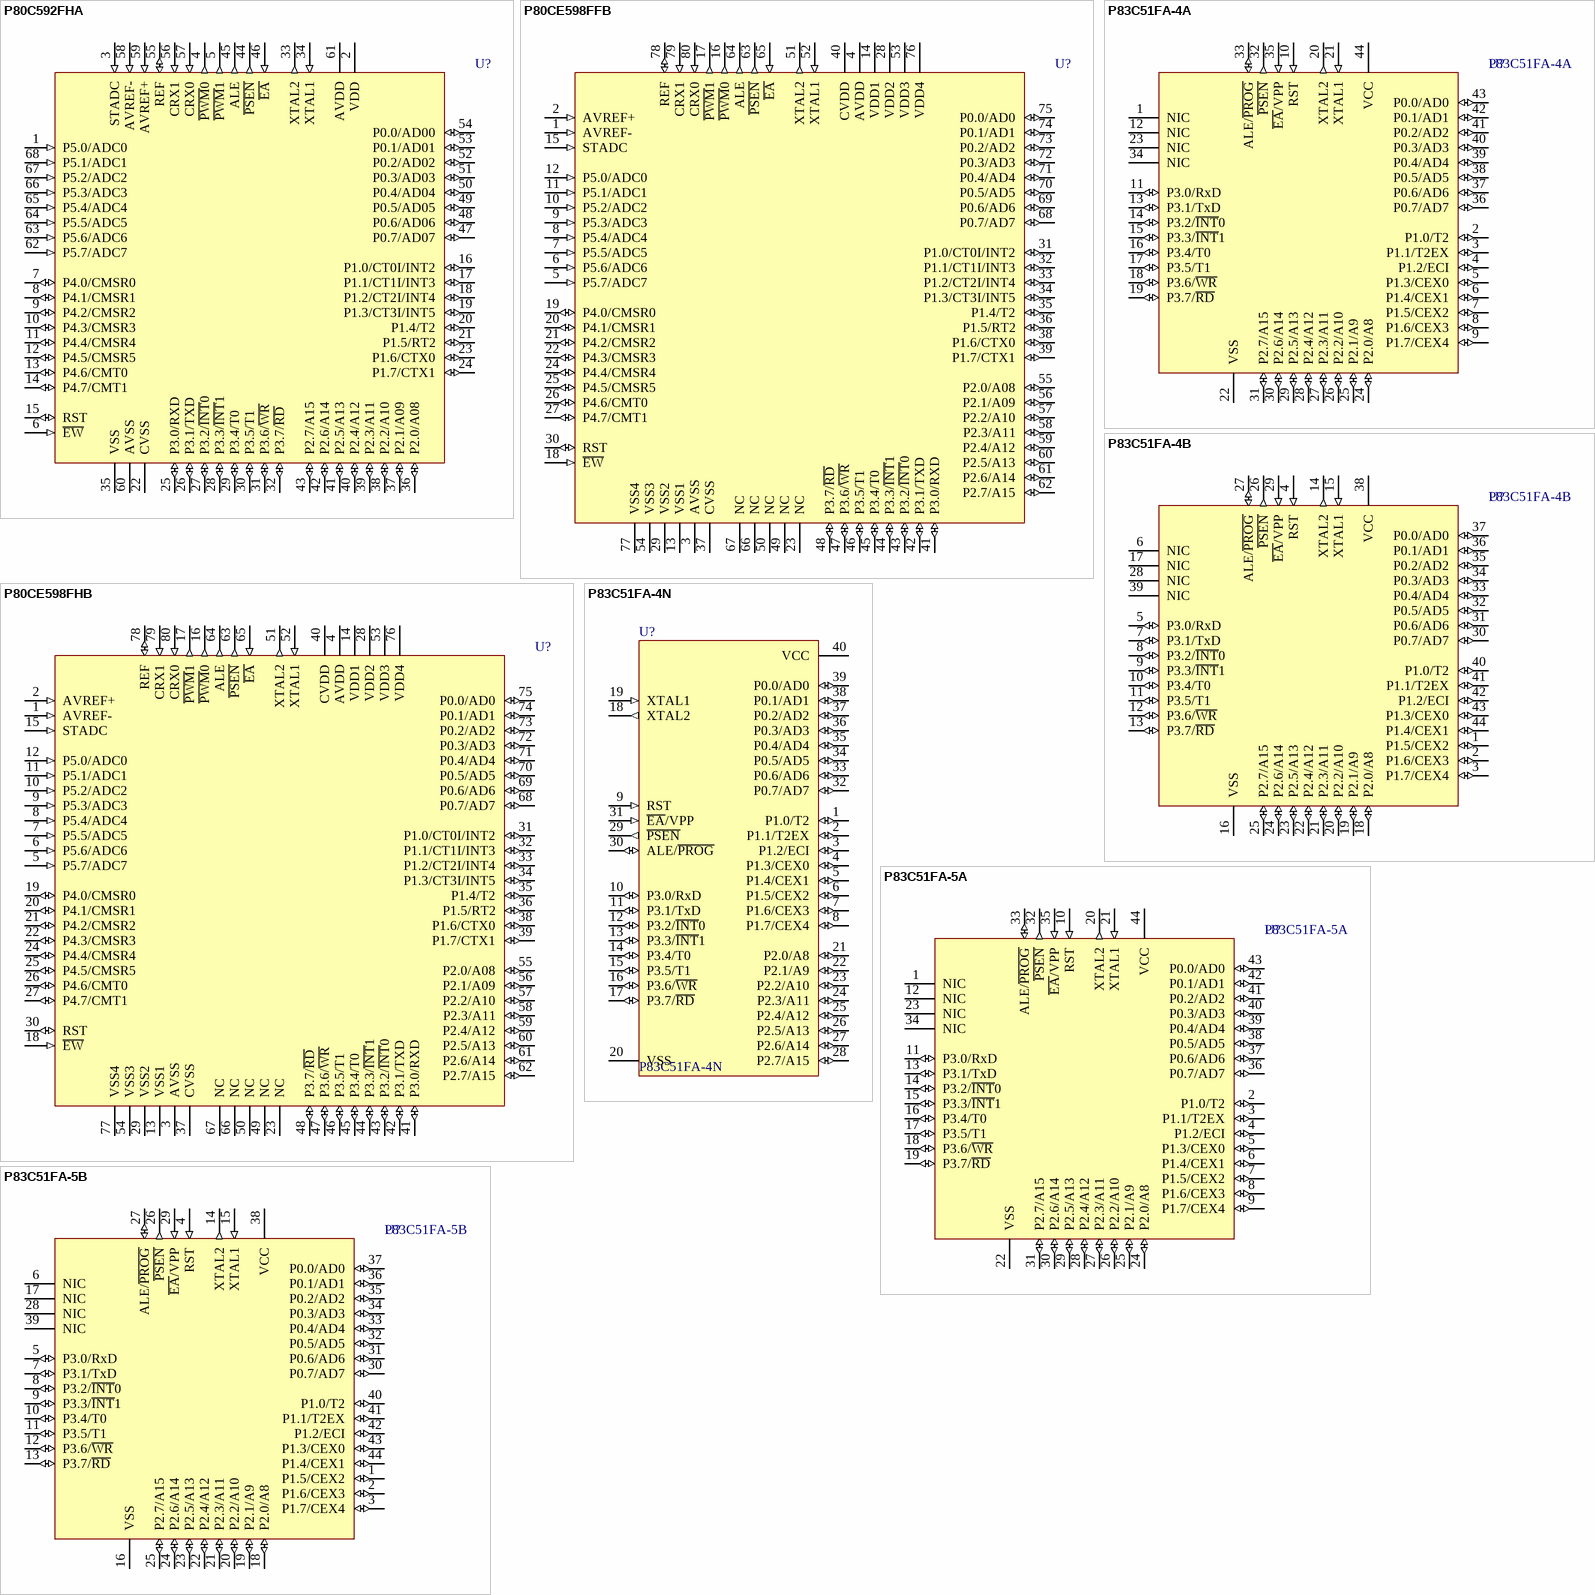
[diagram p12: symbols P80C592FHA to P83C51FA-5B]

## P80C592FHA
designator U?
8-Bit Microcontroller with On-Chip CAN, ROMless
footprint SOT188-2_N (Leaded Chip Carrier, 68-Leads, Body 24.2x24.2mm, Pitch 1.27mm, IPC Medium Density)
footprint SOT188-2_L (Leaded Chip Carrier, 68-Leads, Body 24.2x24.2mm, Pitch 1.27mm, IPC High Density)
footprint SOT188-2_M (Leaded Chip Carrier, 68-Leads, Body 24.2x24.2mm, Pitch 1.27mm, IPC Low Density)
pins: 1 P5.0/ADC0 (in), 2 VDD (power), 3 STADC (in), 4 ~{PWM}0 (out), 5 ~{PWM}1 (out), 6 ~{EW} (in), 7 P4.0/CMSR0 (io), 8 P4.1/CMSR1 (io), 9 P4.2/CMSR2 (io), 10 P4.3/CMSR3 (io), 11 P4.4/CMSR4 (io), 12 P4.5/CMSR5 (io), 13 P4.6/CMT0 (io), 14 P4.7/CMT1 (io), 15 RST (io), 16 P1.0/CT0I/INT2 (io), 17 P1.1/CT1I/INT3 (io), 18 P1.2/CT2I/INT4 (io), 19 P1.3/CT3I/INT5 (io), 20 P1.4/T2 (io), 21 P1.5/RT2 (io), 22 CVSS (power), 23 P1.6/CTX0 (io), 24 P1.7/CTX1 (io), 25 P3.0/RXD (io), 26 P3.1/TXD (io), 27 P3.2/~{INT}0 (io), 28 P3.3/~{INT}1 (io), 29 P3.4/T0 (io), 30 P3.5/T1 (io), 31 P3.6/~{WR} (io), 32 P3.7/~{RD} (io), 33 XTAL2 (out), 34 XTAL1 (in), 35 VSS (power), 36 P2.0/A08 (io), 37 P2.1/A09 (io), 38 P2.2/A10 (io), 39 P2.3/A11 (io), 40 P2.4/A12 (io), 41 P2.5/A13 (io), 42 P2.6/A14 (io), 43 P2.7/A15 (io), 44 ~{PSEN} (out), 45 ALE (out), 46 ~{EA} (in), 47 P0.7/AD07 (io), 48 P0.6/AD06 (io), 49 P0.5/AD05 (io), 50 P0.4/AD04 (io), 51 P0.3/AD03 (io), 52 P0.2/AD02 (io), 53 P0.1/AD01 (io), 54 P0.0/AD00 (io), 55 REF (io), 56 CRX1 (in), 57 CRX0 (in), 58 AVREF- (in), 59 AVREF+ (in), 60 AVSS (power), 61 AVDD (power), 62 P5.7/ADC7 (in), 63 P5.6/ADC6 (in), 64 P5.5/ADC5 (in), 65 P5.4/ADC4 (in), 66 P5.3/ADC3 (in), 67 P5.2/ADC2 (in), 68 P5.1/ADC1 (in)

## P80CE598FFB
designator U?
8-Bit Microcontroller with On-Chip CAN, ROMless
footprint SOT318-1_N (QFP, 80-Leads, Body 20x14mm, Pitch 0.8mm, IPC Medium Density)
footprint SOT318-1_L (QFP, 80-Leads, Body 20x14mm, Pitch 0.8mm, IPC High Density)
footprint SOT318-1_M (QFP, 80-Leads, Body 20x14mm, Pitch 0.8mm, IPC Low Density)
pins: 1 AVREF- (in), 2 AVREF+ (in), 3 AVSS (power), 4 AVDD (power), 5 P5.7/ADC7 (in), 6 P5.6/ADC6 (in), 7 P5.5/ADC5 (in), 8 P5.4/ADC4 (in), 9 P5.3/ADC3 (in), 10 P5.2/ADC2 (in), 11 P5.1/ADC1 (in), 12 P5.0/ADC0 (in), 13 VSS1 (power), 14 VDD1 (power), 15 STADC (in), 16 ~{PWM}0 (out), 17 ~{PWM}1 (out), 18 ~{EW} (in), 19 P4.0/CMSR0 (io), 20 P4.1/CMSR1 (io), 21 P4.2/CMSR2 (io), 22 P4.3/CMSR3 (io), 23 NC, 24 P4.4/CMSR4 (io), 25 P4.5/CMSR5 (io), 26 P4.6/CMT0 (io), 27 P4.7/CMT1 (io), 28 VDD2 (power), 29 VSS2 (power), 30 RST (io), 31 P1.0/CT0I/INT2 (io), 32 P1.1/CT1I/INT3 (io), 33 P1.2/CT2I/INT4 (io), 34 P1.3/CT3I/INT5 (io), 35 P1.4/T2 (io), 36 P1.5/RT2 (io), 37 CVSS (power), 38 P1.6/CTX0 (io), 39 P1.7/CTX1 (io), 40 CVDD (power), 41 P3.0/RXD (io), 42 P3.1/TXD (io), 43 P3.2/~{INT}0 (io), 44 P3.3/~{INT}1 (io), 45 P3.4/T0 (io), 46 P3.5/T1 (io), 47 P3.6/~{WR} (io), 48 P3.7/~{RD} (io), 49 NC, 50 NC, 51 XTAL2 (out), 52 XTAL1 (in), 53 VDD3 (power), 54 VSS3 (power), 55 P2.0/A08 (io), 56 P2.1/A09 (io), 57 P2.2/A10 (io), 58 P2.3/A11 (io), 59 P2.4/A12 (io), 60 P2.5/A13 (io), 61 P2.6/A14 (io), 62 P2.7/A15 (io), 63 ~{PSEN} (out), 64 ALE (out), 65 ~{EA} (in), 66 NC, 67 NC, 68 P0.7/AD7 (io), 69 P0.6/AD6 (io), 70 P0.5/AD5 (io), 71 P0.4/AD4 (io), 72 P0.3/AD3 (io), 73 P0.2/AD2 (io), 74 P0.1/AD1 (io), 75 P0.0/AD0 (io), 76 VDD4 (power), 77 VSS4 (power), 78 REF (io), 79 CRX1 (in), 80 CRX0 (in)

## P80CE598FHB
designator U?
8-Bit Microcontroller with On-Chip CAN, ROMless
footprint SOT318-1_N (QFP, 80-Leads, Body 20x14mm, Pitch 0.8mm, IPC Medium Density)
footprint SOT318-1_L (QFP, 80-Leads, Body 20x14mm, Pitch 0.8mm, IPC High Density)
footprint SOT318-1_M (QFP, 80-Leads, Body 20x14mm, Pitch 0.8mm, IPC Low Density)
pins: 1 AVREF- (in), 2 AVREF+ (in), 3 AVSS (power), 4 AVDD (power), 5 P5.7/ADC7 (in), 6 P5.6/ADC6 (in), 7 P5.5/ADC5 (in), 8 P5.4/ADC4 (in), 9 P5.3/ADC3 (in), 10 P5.2/ADC2 (in), 11 P5.1/ADC1 (in), 12 P5.0/ADC0 (in), 13 VSS1 (power), 14 VDD1 (power), 15 STADC (in), 16 ~{PWM}0 (out), 17 ~{PWM}1 (out), 18 ~{EW} (in), 19 P4.0/CMSR0 (io), 20 P4.1/CMSR1 (io), 21 P4.2/CMSR2 (io), 22 P4.3/CMSR3 (io), 23 NC, 24 P4.4/CMSR4 (io), 25 P4.5/CMSR5 (io), 26 P4.6/CMT0 (io), 27 P4.7/CMT1 (io), 28 VDD2 (power), 29 VSS2 (power), 30 RST (io), 31 P1.0/CT0I/INT2 (io), 32 P1.1/CT1I/INT3 (io), 33 P1.2/CT2I/INT4 (io), 34 P1.3/CT3I/INT5 (io), 35 P1.4/T2 (io), 36 P1.5/RT2 (io), 37 CVSS (power), 38 P1.6/CTX0 (io), 39 P1.7/CTX1 (io), 40 CVDD (power), 41 P3.0/RXD (io), 42 P3.1/TXD (io), 43 P3.2/~{INT}0 (io), 44 P3.3/~{INT}1 (io), 45 P3.4/T0 (io), 46 P3.5/T1 (io), 47 P3.6/~{WR} (io), 48 P3.7/~{RD} (io), 49 NC, 50 NC, 51 XTAL2 (out), 52 XTAL1 (in), 53 VDD3 (power), 54 VSS3 (power), 55 P2.0/A08 (io), 56 P2.1/A09 (io), 57 P2.2/A10 (io), 58 P2.3/A11 (io), 59 P2.4/A12 (io), 60 P2.5/A13 (io), 61 P2.6/A14 (io), 62 P2.7/A15 (io), 63 ~{PSEN} (out), 64 ALE (out), 65 ~{EA} (in), 66 NC, 67 NC, 68 P0.7/AD7 (io), 69 P0.6/AD6 (io), 70 P0.5/AD5 (io), 71 P0.4/AD4 (io), 72 P0.3/AD3 (io), 73 P0.2/AD2 (io), 74 P0.1/AD1 (io), 75 P0.0/AD0 (io), 76 VDD4 (power), 77 VSS4 (power), 78 REF (io), 79 CRX1 (in), 80 CRX0 (in)

## P83C51FA-4A
designator U?
80C51 8-Bit Microcontroller Family: 256 B RAM, 8 kB ROM, 2.7V-5.5V, Low Power, High Speed
footprint SOT187-2_N (Leaded Chip Carrier, 44-Leads, Body 16.6x16.6mm, Pitch 1.27mm, IPC Medium Density)
footprint SOT187-2_L (Leaded Chip Carrier, 44-Leads, Body 16.6x16.6mm, Pitch 1.27mm, IPC High Density)
footprint SOT187-2_M (Leaded Chip Carrier, 44-Leads, Body 16.6x16.6mm, Pitch 1.27mm, IPC Low Density)
pins: 1 NIC, 2 P1.0/T2 (io), 3 P1.1/T2EX (io), 4 P1.2/ECI (io), 5 P1.3/CEX0 (io), 6 P1.4/CEX1 (io), 7 P1.5/CEX2 (io), 8 P1.6/CEX3 (io), 9 P1.7/CEX4 (io), 10 RST (in), 11 P3.0/RxD (io), 12 NIC, 13 P3.1/TxD (io), 14 P3.2/~{INT}0 (io), 15 P3.3/~{INT}1 (io), 16 P3.4/T0 (io), 17 P3.5/T1 (io), 18 P3.6/~{WR} (io), 19 P3.7/~{RD} (io), 20 XTAL2 (out), 21 XTAL1 (in), 22 VSS (power), 23 NIC, 24 P2.0/A8 (io), 25 P2.1/A9 (io), 26 P2.2/A10 (io), 27 P2.3/A11 (io), 28 P2.4/A12 (io), 29 P2.5/A13 (io), 30 P2.6/A14 (io), 31 P2.7/A15 (io), 32 ~{PSEN} (out), 33 ALE/~{PROG} (io), 34 NIC, 35 ~{EA}/VPP (in), 36 P0.7/AD7 (io), 37 P0.6/AD6 (io), 38 P0.5/AD5 (io), 39 P0.4/AD4 (io), 40 P0.3/AD3 (io), 41 P0.2/AD2 (io), 42 P0.1/AD1 (io), 43 P0.0/AD0 (io), 44 VCC (power)

## P83C51FA-4B
designator U?
80C51 8-Bit Microcontroller Family: 256 B RAM, 8 kB ROM, 2.7V-5.5V, Low Power, High Speed
footprint SOT307-2_N (QFP, 44-Leads, Body 10x10mm, Pitch 0.8mm, IPC Medium Density)
footprint SOT307-2_L (QFP, 44-Leads, Body 10x10mm, Pitch 0.8mm, IPC High Density)
footprint SOT307-2_M (QFP, 44-Leads, Body 10x10mm, Pitch 0.8mm, IPC Low Density)
pins: 1 P1.5/CEX2 (io), 2 P1.6/CEX3 (io), 3 P1.7/CEX4 (io), 4 RST (in), 5 P3.0/RxD (io), 6 NIC, 7 P3.1/TxD (io), 8 P3.2/~{INT}0 (io), 9 P3.3/~{INT}1 (io), 10 P3.4/T0 (io), 11 P3.5/T1 (io), 12 P3.6/~{WR} (io), 13 P3.7/~{RD} (io), 14 XTAL2 (out), 15 XTAL1 (in), 16 VSS (power), 17 NIC, 18 P2.0/A8 (io), 19 P2.1/A9 (io), 20 P2.2/A10 (io), 21 P2.3/A11 (io), 22 P2.4/A12 (io), 23 P2.5/A13 (io), 24 P2.6/A14 (io), 25 P2.7/A15 (io), 26 ~{PSEN} (out), 27 ALE/~{PROG} (io), 28 NIC, 29 ~{EA}/VPP (in), 30 P0.7/AD7 (io), 31 P0.6/AD6 (io), 32 P0.5/AD5 (io), 33 P0.4/AD4 (io), 34 P0.3/AD3 (io), 35 P0.2/AD2 (io), 36 P0.1/AD1 (io), 37 P0.0/AD0 (io), 38 VCC (power), 39 NIC, 40 P1.0/T2 (io), 41 P1.1/T2EX (io), 42 P1.2/ECI (io), 43 P1.3/CEX0 (io), 44 P1.4/CEX1 (io)

## P83C51FA-4N
designator U?
80C51 8-Bit Microcontroller Family: 256 B RAM, 8 kB ROM, 2.7V-5.5V, Low Power, High Speed
footprint SOT129-1 (DIP, Plastic; 40 Leads; Row Spacing 15.24 mm; Pitch 2.54 mm)
pins: 1 P1.0/T2 (io), 2 P1.1/T2EX (io), 3 P1.2/ECI (io), 4 P1.3/CEX0 (io), 5 P1.4/CEX1 (io), 6 P1.5/CEX2 (io), 7 P1.6/CEX3 (io), 8 P1.7/CEX4 (io), 9 RST (in), 10 P3.0/RxD (io), 11 P3.1/TxD (io), 12 P3.2/~{INT}0 (io), 13 P3.3/~{INT}1 (io), 14 P3.4/T0 (io), 15 P3.5/T1 (io), 16 P3.6/~{WR} (io), 17 P3.7/~{RD} (io), 18 XTAL2 (out), 19 XTAL1 (in), 20 VSS (power), 21 P2.0/A8 (io), 22 P2.1/A9 (io), 23 P2.2/A10 (io), 24 P2.3/A11 (io), 25 P2.4/A12 (io), 26 P2.5/A13 (io), 27 P2.6/A14 (io), 28 P2.7/A15 (io), 29 ~{PSEN} (out), 30 ALE/~{PROG} (io), 31 ~{EA}/VPP (in), 32 P0.7/AD7 (io), 33 P0.6/AD6 (io), 34 P0.5/AD5 (io), 35 P0.4/AD4 (io), 36 P0.3/AD3 (io), 37 P0.2/AD2 (io), 38 P0.1/AD1 (io), 39 P0.0/AD0 (io), 40 VCC (power)

## P83C51FA-5A
designator U?
80C51 8-Bit Microcontroller Family: 256 B RAM, 8 kB ROM, 2.7V-5.5V, Low Power, High Speed
footprint SOT187-2_N (Leaded Chip Carrier, 44-Leads, Body 16.6x16.6mm, Pitch 1.27mm, IPC Medium Density)
footprint SOT187-2_L (Leaded Chip Carrier, 44-Leads, Body 16.6x16.6mm, Pitch 1.27mm, IPC High Density)
footprint SOT187-2_M (Leaded Chip Carrier, 44-Leads, Body 16.6x16.6mm, Pitch 1.27mm, IPC Low Density)
pins: 1 NIC, 2 P1.0/T2 (io), 3 P1.1/T2EX (io), 4 P1.2/ECI (io), 5 P1.3/CEX0 (io), 6 P1.4/CEX1 (io), 7 P1.5/CEX2 (io), 8 P1.6/CEX3 (io), 9 P1.7/CEX4 (io), 10 RST (in), 11 P3.0/RxD (io), 12 NIC, 13 P3.1/TxD (io), 14 P3.2/~{INT}0 (io), 15 P3.3/~{INT}1 (io), 16 P3.4/T0 (io), 17 P3.5/T1 (io), 18 P3.6/~{WR} (io), 19 P3.7/~{RD} (io), 20 XTAL2 (out), 21 XTAL1 (in), 22 VSS (power), 23 NIC, 24 P2.0/A8 (io), 25 P2.1/A9 (io), 26 P2.2/A10 (io), 27 P2.3/A11 (io), 28 P2.4/A12 (io), 29 P2.5/A13 (io), 30 P2.6/A14 (io), 31 P2.7/A15 (io), 32 ~{PSEN} (out), 33 ALE/~{PROG} (io), 34 NIC, 35 ~{EA}/VPP (in), 36 P0.7/AD7 (io), 37 P0.6/AD6 (io), 38 P0.5/AD5 (io), 39 P0.4/AD4 (io), 40 P0.3/AD3 (io), 41 P0.2/AD2 (io), 42 P0.1/AD1 (io), 43 P0.0/AD0 (io), 44 VCC (power)

## P83C51FA-5B
designator U?
80C51 8-Bit Microcontroller Family: 256 B RAM, 8 kB ROM, 2.7V-5.5V, Low Power, High Speed
footprint SOT307-2_N (QFP, 44-Leads, Body 10x10mm, Pitch 0.8mm, IPC Medium Density)
footprint SOT307-2_L (QFP, 44-Leads, Body 10x10mm, Pitch 0.8mm, IPC High Density)
footprint SOT307-2_M (QFP, 44-Leads, Body 10x10mm, Pitch 0.8mm, IPC Low Density)
pins: 1 P1.5/CEX2 (io), 2 P1.6/CEX3 (io), 3 P1.7/CEX4 (io), 4 RST (in), 5 P3.0/RxD (io), 6 NIC, 7 P3.1/TxD (io), 8 P3.2/~{INT}0 (io), 9 P3.3/~{INT}1 (io), 10 P3.4/T0 (io), 11 P3.5/T1 (io), 12 P3.6/~{WR} (io), 13 P3.7/~{RD} (io), 14 XTAL2 (out), 15 XTAL1 (in), 16 VSS (power), 17 NIC, 18 P2.0/A8 (io), 19 P2.1/A9 (io), 20 P2.2/A10 (io), 21 P2.3/A11 (io), 22 P2.4/A12 (io), 23 P2.5/A13 (io), 24 P2.6/A14 (io), 25 P2.7/A15 (io), 26 ~{PSEN} (out), 27 ALE/~{PROG} (io), 28 NIC, 29 ~{EA}/VPP (in), 30 P0.7/AD7 (io), 31 P0.6/AD6 (io), 32 P0.5/AD5 (io), 33 P0.4/AD4 (io), 34 P0.3/AD3 (io), 35 P0.2/AD2 (io), 36 P0.1/AD1 (io), 37 P0.0/AD0 (io), 38 VCC (power), 39 NIC, 40 P1.0/T2 (io), 41 P1.1/T2EX (io), 42 P1.2/ECI (io), 43 P1.3/CEX0 (io), 44 P1.4/CEX1 (io)

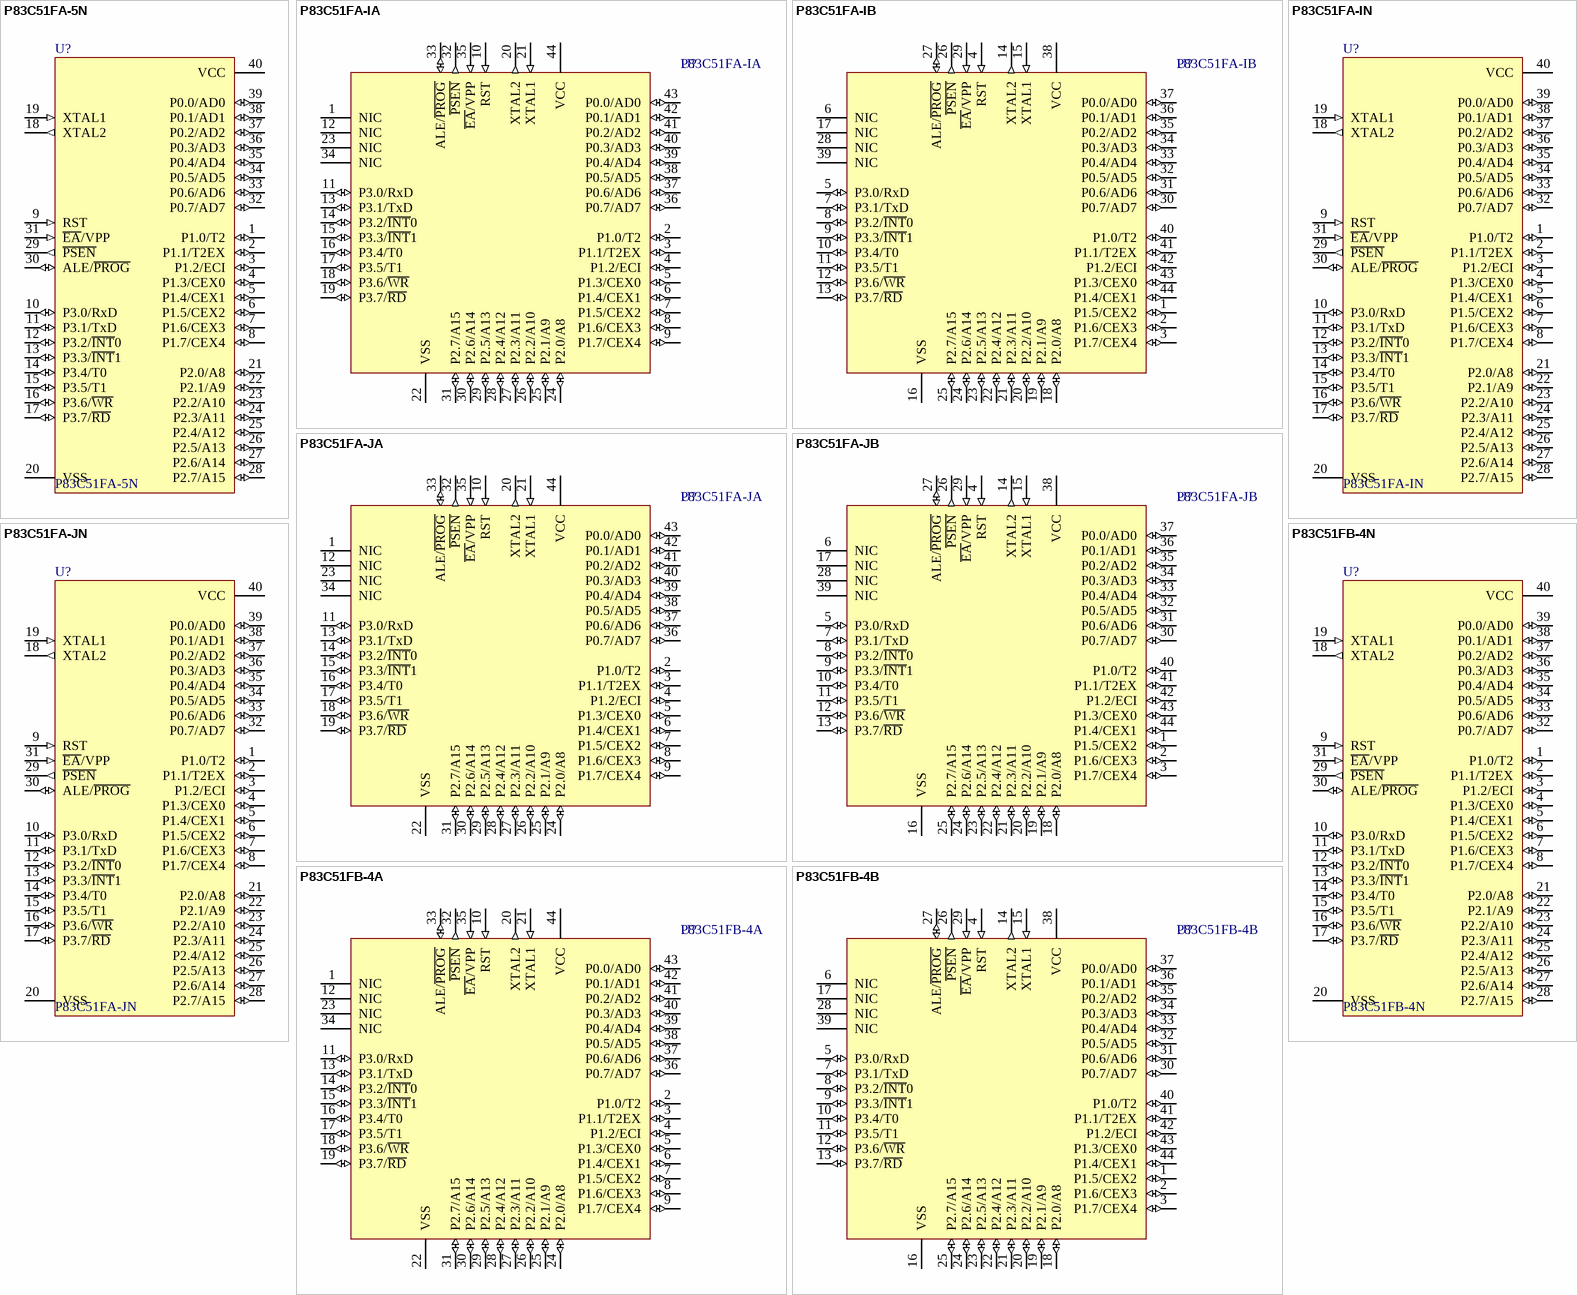
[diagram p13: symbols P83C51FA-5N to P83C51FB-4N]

## P83C51FA-5N
designator U?
80C51 8-Bit Microcontroller Family: 256 B RAM, 8 kB ROM, 2.7V-5.5V, Low Power, High Speed
footprint SOT129-1 (DIP, Plastic; 40 Leads; Row Spacing 15.24 mm; Pitch 2.54 mm)
pins: 1 P1.0/T2 (io), 2 P1.1/T2EX (io), 3 P1.2/ECI (io), 4 P1.3/CEX0 (io), 5 P1.4/CEX1 (io), 6 P1.5/CEX2 (io), 7 P1.6/CEX3 (io), 8 P1.7/CEX4 (io), 9 RST (in), 10 P3.0/RxD (io), 11 P3.1/TxD (io), 12 P3.2/~{INT}0 (io), 13 P3.3/~{INT}1 (io), 14 P3.4/T0 (io), 15 P3.5/T1 (io), 16 P3.6/~{WR} (io), 17 P3.7/~{RD} (io), 18 XTAL2 (out), 19 XTAL1 (in), 20 VSS (power), 21 P2.0/A8 (io), 22 P2.1/A9 (io), 23 P2.2/A10 (io), 24 P2.3/A11 (io), 25 P2.4/A12 (io), 26 P2.5/A13 (io), 27 P2.6/A14 (io), 28 P2.7/A15 (io), 29 ~{PSEN} (out), 30 ALE/~{PROG} (io), 31 ~{EA}/VPP (in), 32 P0.7/AD7 (io), 33 P0.6/AD6 (io), 34 P0.5/AD5 (io), 35 P0.4/AD4 (io), 36 P0.3/AD3 (io), 37 P0.2/AD2 (io), 38 P0.1/AD1 (io), 39 P0.0/AD0 (io), 40 VCC (power)

## P83C51FA-IA
designator U?
80C51 8-Bit Microcontroller Family: 256 B RAM, 8 kB ROM, 5V, Low Power, High Speed
footprint SOT187-2_N (Leaded Chip Carrier, 44-Leads, Body 16.6x16.6mm, Pitch 1.27mm, IPC Medium Density)
footprint SOT187-2_L (Leaded Chip Carrier, 44-Leads, Body 16.6x16.6mm, Pitch 1.27mm, IPC High Density)
footprint SOT187-2_M (Leaded Chip Carrier, 44-Leads, Body 16.6x16.6mm, Pitch 1.27mm, IPC Low Density)
pins: 1 NIC, 2 P1.0/T2 (io), 3 P1.1/T2EX (io), 4 P1.2/ECI (io), 5 P1.3/CEX0 (io), 6 P1.4/CEX1 (io), 7 P1.5/CEX2 (io), 8 P1.6/CEX3 (io), 9 P1.7/CEX4 (io), 10 RST (in), 11 P3.0/RxD (io), 12 NIC, 13 P3.1/TxD (io), 14 P3.2/~{INT}0 (io), 15 P3.3/~{INT}1 (io), 16 P3.4/T0 (io), 17 P3.5/T1 (io), 18 P3.6/~{WR} (io), 19 P3.7/~{RD} (io), 20 XTAL2 (out), 21 XTAL1 (in), 22 VSS (power), 23 NIC, 24 P2.0/A8 (io), 25 P2.1/A9 (io), 26 P2.2/A10 (io), 27 P2.3/A11 (io), 28 P2.4/A12 (io), 29 P2.5/A13 (io), 30 P2.6/A14 (io), 31 P2.7/A15 (io), 32 ~{PSEN} (out), 33 ALE/~{PROG} (io), 34 NIC, 35 ~{EA}/VPP (in), 36 P0.7/AD7 (io), 37 P0.6/AD6 (io), 38 P0.5/AD5 (io), 39 P0.4/AD4 (io), 40 P0.3/AD3 (io), 41 P0.2/AD2 (io), 42 P0.1/AD1 (io), 43 P0.0/AD0 (io), 44 VCC (power)

## P83C51FA-IB
designator U?
80C51 8-Bit Microcontroller Family: 256 B RAM, 8 kB ROM, 5V, Low Power, High Speed
footprint SOT307-2_N (QFP, 44-Leads, Body 10x10mm, Pitch 0.8mm, IPC Medium Density)
footprint SOT307-2_L (QFP, 44-Leads, Body 10x10mm, Pitch 0.8mm, IPC High Density)
footprint SOT307-2_M (QFP, 44-Leads, Body 10x10mm, Pitch 0.8mm, IPC Low Density)
pins: 1 P1.5/CEX2 (io), 2 P1.6/CEX3 (io), 3 P1.7/CEX4 (io), 4 RST (in), 5 P3.0/RxD (io), 6 NIC, 7 P3.1/TxD (io), 8 P3.2/~{INT}0 (io), 9 P3.3/~{INT}1 (io), 10 P3.4/T0 (io), 11 P3.5/T1 (io), 12 P3.6/~{WR} (io), 13 P3.7/~{RD} (io), 14 XTAL2 (out), 15 XTAL1 (in), 16 VSS (power), 17 NIC, 18 P2.0/A8 (io), 19 P2.1/A9 (io), 20 P2.2/A10 (io), 21 P2.3/A11 (io), 22 P2.4/A12 (io), 23 P2.5/A13 (io), 24 P2.6/A14 (io), 25 P2.7/A15 (io), 26 ~{PSEN} (out), 27 ALE/~{PROG} (io), 28 NIC, 29 ~{EA}/VPP (in), 30 P0.7/AD7 (io), 31 P0.6/AD6 (io), 32 P0.5/AD5 (io), 33 P0.4/AD4 (io), 34 P0.3/AD3 (io), 35 P0.2/AD2 (io), 36 P0.1/AD1 (io), 37 P0.0/AD0 (io), 38 VCC (power), 39 NIC, 40 P1.0/T2 (io), 41 P1.1/T2EX (io), 42 P1.2/ECI (io), 43 P1.3/CEX0 (io), 44 P1.4/CEX1 (io)

## P83C51FA-IN
designator U?
80C51 8-Bit Microcontroller Family: 256 B RAM, 8 kB ROM, 5V, Low Power, High Speed
footprint SOT129-1 (DIP, Plastic; 40 Leads; Row Spacing 15.24 mm; Pitch 2.54 mm)
pins: 1 P1.0/T2 (io), 2 P1.1/T2EX (io), 3 P1.2/ECI (io), 4 P1.3/CEX0 (io), 5 P1.4/CEX1 (io), 6 P1.5/CEX2 (io), 7 P1.6/CEX3 (io), 8 P1.7/CEX4 (io), 9 RST (in), 10 P3.0/RxD (io), 11 P3.1/TxD (io), 12 P3.2/~{INT}0 (io), 13 P3.3/~{INT}1 (io), 14 P3.4/T0 (io), 15 P3.5/T1 (io), 16 P3.6/~{WR} (io), 17 P3.7/~{RD} (io), 18 XTAL2 (out), 19 XTAL1 (in), 20 VSS (power), 21 P2.0/A8 (io), 22 P2.1/A9 (io), 23 P2.2/A10 (io), 24 P2.3/A11 (io), 25 P2.4/A12 (io), 26 P2.5/A13 (io), 27 P2.6/A14 (io), 28 P2.7/A15 (io), 29 ~{PSEN} (out), 30 ALE/~{PROG} (io), 31 ~{EA}/VPP (in), 32 P0.7/AD7 (io), 33 P0.6/AD6 (io), 34 P0.5/AD5 (io), 35 P0.4/AD4 (io), 36 P0.3/AD3 (io), 37 P0.2/AD2 (io), 38 P0.1/AD1 (io), 39 P0.0/AD0 (io), 40 VCC (power)

## P83C51FA-JA
designator U?
80C51 8-Bit Microcontroller Family: 256 B RAM, 8 kB ROM, 5V, Low Power, High Speed
footprint SOT187-2_N (Leaded Chip Carrier, 44-Leads, Body 16.6x16.6mm, Pitch 1.27mm, IPC Medium Density)
footprint SOT187-2_L (Leaded Chip Carrier, 44-Leads, Body 16.6x16.6mm, Pitch 1.27mm, IPC High Density)
footprint SOT187-2_M (Leaded Chip Carrier, 44-Leads, Body 16.6x16.6mm, Pitch 1.27mm, IPC Low Density)
pins: 1 NIC, 2 P1.0/T2 (io), 3 P1.1/T2EX (io), 4 P1.2/ECI (io), 5 P1.3/CEX0 (io), 6 P1.4/CEX1 (io), 7 P1.5/CEX2 (io), 8 P1.6/CEX3 (io), 9 P1.7/CEX4 (io), 10 RST (in), 11 P3.0/RxD (io), 12 NIC, 13 P3.1/TxD (io), 14 P3.2/~{INT}0 (io), 15 P3.3/~{INT}1 (io), 16 P3.4/T0 (io), 17 P3.5/T1 (io), 18 P3.6/~{WR} (io), 19 P3.7/~{RD} (io), 20 XTAL2 (out), 21 XTAL1 (in), 22 VSS (power), 23 NIC, 24 P2.0/A8 (io), 25 P2.1/A9 (io), 26 P2.2/A10 (io), 27 P2.3/A11 (io), 28 P2.4/A12 (io), 29 P2.5/A13 (io), 30 P2.6/A14 (io), 31 P2.7/A15 (io), 32 ~{PSEN} (out), 33 ALE/~{PROG} (io), 34 NIC, 35 ~{EA}/VPP (in), 36 P0.7/AD7 (io), 37 P0.6/AD6 (io), 38 P0.5/AD5 (io), 39 P0.4/AD4 (io), 40 P0.3/AD3 (io), 41 P0.2/AD2 (io), 42 P0.1/AD1 (io), 43 P0.0/AD0 (io), 44 VCC (power)

## P83C51FA-JB
designator U?
80C51 8-Bit Microcontroller Family: 256 B RAM, 8 kB ROM, 5V, Low Power, High Speed
footprint SOT307-2_N (QFP, 44-Leads, Body 10x10mm, Pitch 0.8mm, IPC Medium Density)
footprint SOT307-2_L (QFP, 44-Leads, Body 10x10mm, Pitch 0.8mm, IPC High Density)
footprint SOT307-2_M (QFP, 44-Leads, Body 10x10mm, Pitch 0.8mm, IPC Low Density)
pins: 1 P1.5/CEX2 (io), 2 P1.6/CEX3 (io), 3 P1.7/CEX4 (io), 4 RST (in), 5 P3.0/RxD (io), 6 NIC, 7 P3.1/TxD (io), 8 P3.2/~{INT}0 (io), 9 P3.3/~{INT}1 (io), 10 P3.4/T0 (io), 11 P3.5/T1 (io), 12 P3.6/~{WR} (io), 13 P3.7/~{RD} (io), 14 XTAL2 (out), 15 XTAL1 (in), 16 VSS (power), 17 NIC, 18 P2.0/A8 (io), 19 P2.1/A9 (io), 20 P2.2/A10 (io), 21 P2.3/A11 (io), 22 P2.4/A12 (io), 23 P2.5/A13 (io), 24 P2.6/A14 (io), 25 P2.7/A15 (io), 26 ~{PSEN} (out), 27 ALE/~{PROG} (io), 28 NIC, 29 ~{EA}/VPP (in), 30 P0.7/AD7 (io), 31 P0.6/AD6 (io), 32 P0.5/AD5 (io), 33 P0.4/AD4 (io), 34 P0.3/AD3 (io), 35 P0.2/AD2 (io), 36 P0.1/AD1 (io), 37 P0.0/AD0 (io), 38 VCC (power), 39 NIC, 40 P1.0/T2 (io), 41 P1.1/T2EX (io), 42 P1.2/ECI (io), 43 P1.3/CEX0 (io), 44 P1.4/CEX1 (io)

## P83C51FA-JN
designator U?
80C51 8-Bit Microcontroller Family: 256 B RAM, 8 kB ROM, 5V, Low Power, High Speed
footprint SOT129-1 (DIP, Plastic; 40 Leads; Row Spacing 15.24 mm; Pitch 2.54 mm)
pins: 1 P1.0/T2 (io), 2 P1.1/T2EX (io), 3 P1.2/ECI (io), 4 P1.3/CEX0 (io), 5 P1.4/CEX1 (io), 6 P1.5/CEX2 (io), 7 P1.6/CEX3 (io), 8 P1.7/CEX4 (io), 9 RST (in), 10 P3.0/RxD (io), 11 P3.1/TxD (io), 12 P3.2/~{INT}0 (io), 13 P3.3/~{INT}1 (io), 14 P3.4/T0 (io), 15 P3.5/T1 (io), 16 P3.6/~{WR} (io), 17 P3.7/~{RD} (io), 18 XTAL2 (out), 19 XTAL1 (in), 20 VSS (power), 21 P2.0/A8 (io), 22 P2.1/A9 (io), 23 P2.2/A10 (io), 24 P2.3/A11 (io), 25 P2.4/A12 (io), 26 P2.5/A13 (io), 27 P2.6/A14 (io), 28 P2.7/A15 (io), 29 ~{PSEN} (out), 30 ALE/~{PROG} (io), 31 ~{EA}/VPP (in), 32 P0.7/AD7 (io), 33 P0.6/AD6 (io), 34 P0.5/AD5 (io), 35 P0.4/AD4 (io), 36 P0.3/AD3 (io), 37 P0.2/AD2 (io), 38 P0.1/AD1 (io), 39 P0.0/AD0 (io), 40 VCC (power)

## P83C51FB-4A
designator U?
80C51 8-Bit Microcontroller Family: 256 B RAM, 16 kB ROM, 2.7V-5.5V, Low Power, High Speed
footprint SOT187-2_N (Leaded Chip Carrier, 44-Leads, Body 16.6x16.6mm, Pitch 1.27mm, IPC Medium Density)
footprint SOT187-2_L (Leaded Chip Carrier, 44-Leads, Body 16.6x16.6mm, Pitch 1.27mm, IPC High Density)
footprint SOT187-2_M (Leaded Chip Carrier, 44-Leads, Body 16.6x16.6mm, Pitch 1.27mm, IPC Low Density)
pins: 1 NIC, 2 P1.0/T2 (io), 3 P1.1/T2EX (io), 4 P1.2/ECI (io), 5 P1.3/CEX0 (io), 6 P1.4/CEX1 (io), 7 P1.5/CEX2 (io), 8 P1.6/CEX3 (io), 9 P1.7/CEX4 (io), 10 RST (in), 11 P3.0/RxD (io), 12 NIC, 13 P3.1/TxD (io), 14 P3.2/~{INT}0 (io), 15 P3.3/~{INT}1 (io), 16 P3.4/T0 (io), 17 P3.5/T1 (io), 18 P3.6/~{WR} (io), 19 P3.7/~{RD} (io), 20 XTAL2 (out), 21 XTAL1 (in), 22 VSS (power), 23 NIC, 24 P2.0/A8 (io), 25 P2.1/A9 (io), 26 P2.2/A10 (io), 27 P2.3/A11 (io), 28 P2.4/A12 (io), 29 P2.5/A13 (io), 30 P2.6/A14 (io), 31 P2.7/A15 (io), 32 ~{PSEN} (out), 33 ALE/~{PROG} (io), 34 NIC, 35 ~{EA}/VPP (in), 36 P0.7/AD7 (io), 37 P0.6/AD6 (io), 38 P0.5/AD5 (io), 39 P0.4/AD4 (io), 40 P0.3/AD3 (io), 41 P0.2/AD2 (io), 42 P0.1/AD1 (io), 43 P0.0/AD0 (io), 44 VCC (power)

## P83C51FB-4B
designator U?
80C51 8-Bit Microcontroller Family: 256 B RAM, 16 kB ROM, 2.7V-5.5V, Low Power, High Speed
footprint SOT307-2_N (QFP, 44-Leads, Body 10x10mm, Pitch 0.8mm, IPC Medium Density)
footprint SOT307-2_L (QFP, 44-Leads, Body 10x10mm, Pitch 0.8mm, IPC High Density)
footprint SOT307-2_M (QFP, 44-Leads, Body 10x10mm, Pitch 0.8mm, IPC Low Density)
pins: 1 P1.5/CEX2 (io), 2 P1.6/CEX3 (io), 3 P1.7/CEX4 (io), 4 RST (in), 5 P3.0/RxD (io), 6 NIC, 7 P3.1/TxD (io), 8 P3.2/~{INT}0 (io), 9 P3.3/~{INT}1 (io), 10 P3.4/T0 (io), 11 P3.5/T1 (io), 12 P3.6/~{WR} (io), 13 P3.7/~{RD} (io), 14 XTAL2 (out), 15 XTAL1 (in), 16 VSS (power), 17 NIC, 18 P2.0/A8 (io), 19 P2.1/A9 (io), 20 P2.2/A10 (io), 21 P2.3/A11 (io), 22 P2.4/A12 (io), 23 P2.5/A13 (io), 24 P2.6/A14 (io), 25 P2.7/A15 (io), 26 ~{PSEN} (out), 27 ALE/~{PROG} (io), 28 NIC, 29 ~{EA}/VPP (in), 30 P0.7/AD7 (io), 31 P0.6/AD6 (io), 32 P0.5/AD5 (io), 33 P0.4/AD4 (io), 34 P0.3/AD3 (io), 35 P0.2/AD2 (io), 36 P0.1/AD1 (io), 37 P0.0/AD0 (io), 38 VCC (power), 39 NIC, 40 P1.0/T2 (io), 41 P1.1/T2EX (io), 42 P1.2/ECI (io), 43 P1.3/CEX0 (io), 44 P1.4/CEX1 (io)

## P83C51FB-4N
designator U?
80C51 8-Bit Microcontroller Family: 256 B RAM, 16 kB ROM, 2.7V-5.5V, Low Power, High Speed
footprint SOT129-1 (DIP, Plastic; 40 Leads; Row Spacing 15.24 mm; Pitch 2.54 mm)
pins: 1 P1.0/T2 (io), 2 P1.1/T2EX (io), 3 P1.2/ECI (io), 4 P1.3/CEX0 (io), 5 P1.4/CEX1 (io), 6 P1.5/CEX2 (io), 7 P1.6/CEX3 (io), 8 P1.7/CEX4 (io), 9 RST (in), 10 P3.0/RxD (io), 11 P3.1/TxD (io), 12 P3.2/~{INT}0 (io), 13 P3.3/~{INT}1 (io), 14 P3.4/T0 (io), 15 P3.5/T1 (io), 16 P3.6/~{WR} (io), 17 P3.7/~{RD} (io), 18 XTAL2 (out), 19 XTAL1 (in), 20 VSS (power), 21 P2.0/A8 (io), 22 P2.1/A9 (io), 23 P2.2/A10 (io), 24 P2.3/A11 (io), 25 P2.4/A12 (io), 26 P2.5/A13 (io), 27 P2.6/A14 (io), 28 P2.7/A15 (io), 29 ~{PSEN} (out), 30 ALE/~{PROG} (io), 31 ~{EA}/VPP (in), 32 P0.7/AD7 (io), 33 P0.6/AD6 (io), 34 P0.5/AD5 (io), 35 P0.4/AD4 (io), 36 P0.3/AD3 (io), 37 P0.2/AD2 (io), 38 P0.1/AD1 (io), 39 P0.0/AD0 (io), 40 VCC (power)

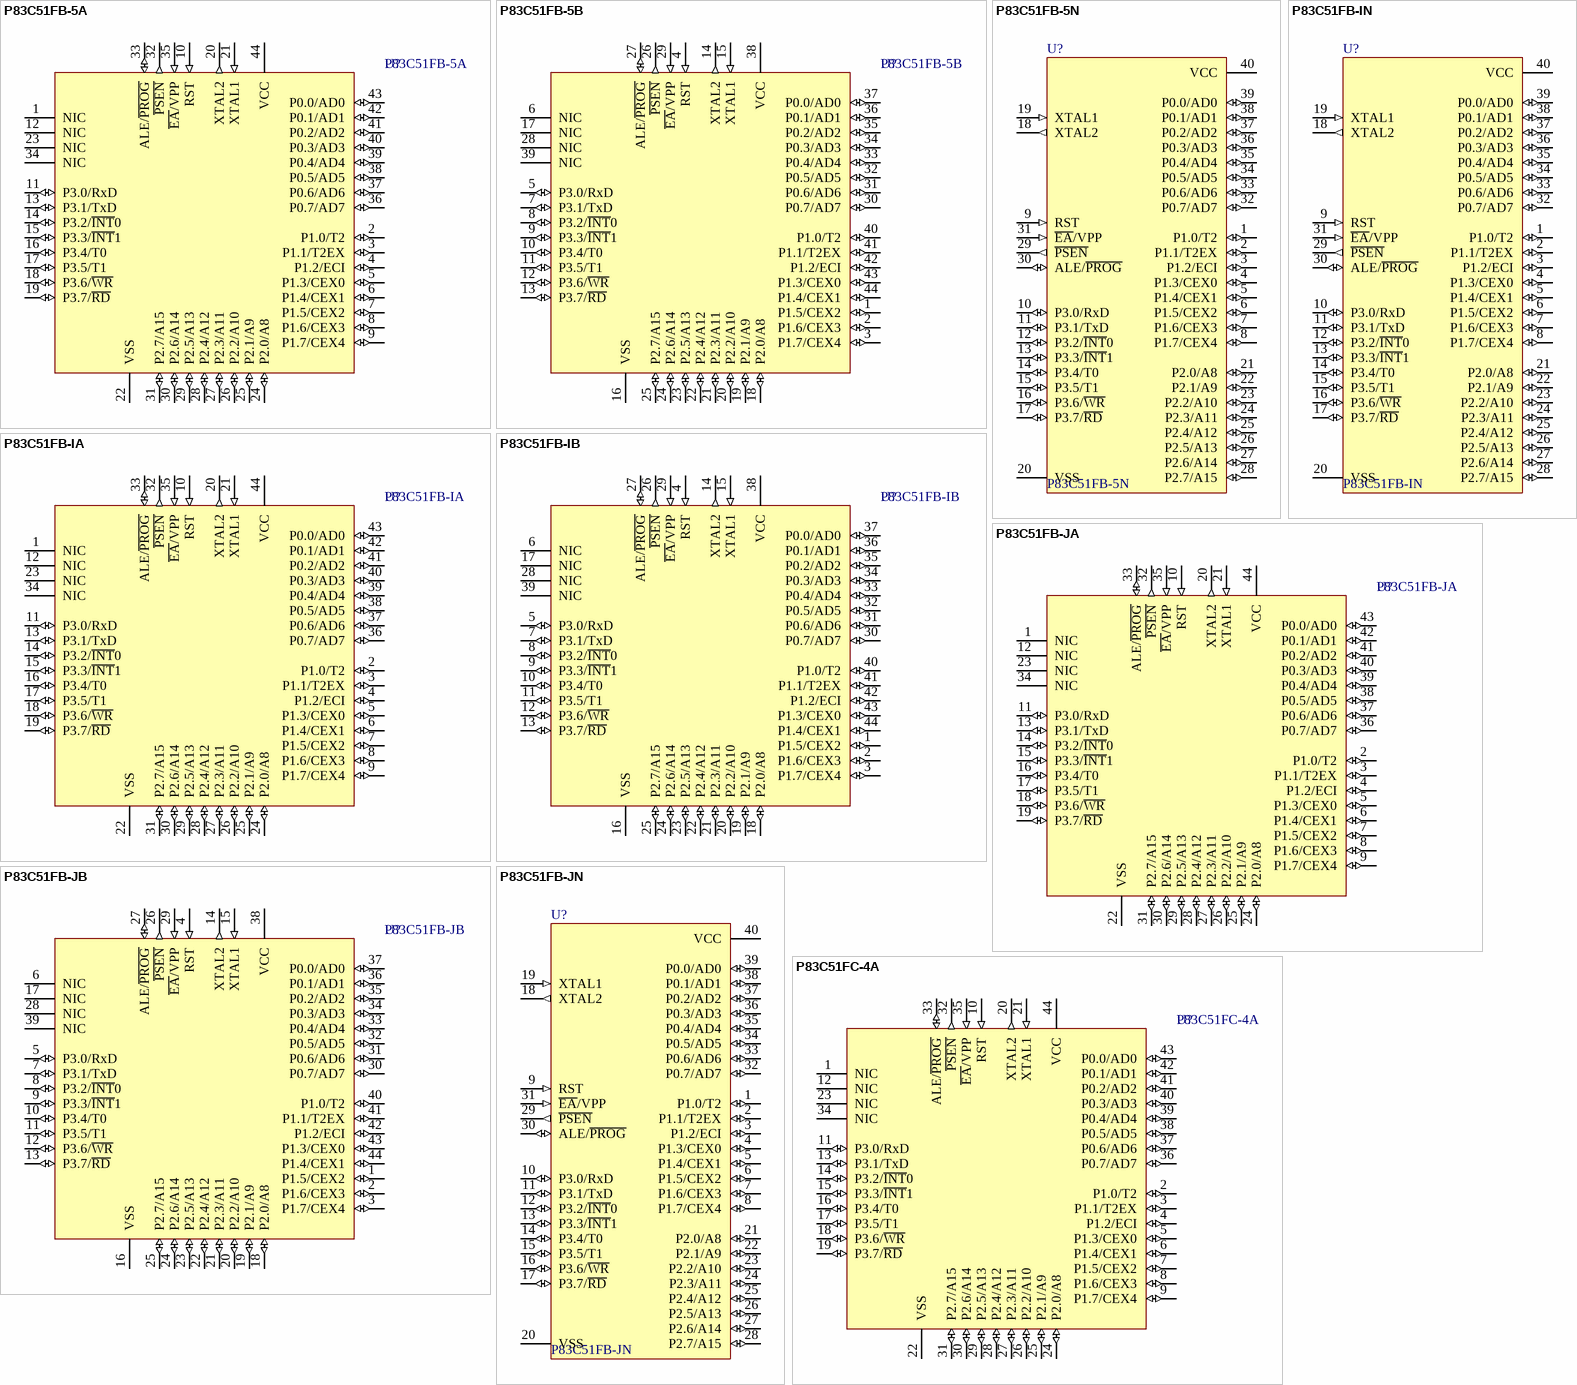
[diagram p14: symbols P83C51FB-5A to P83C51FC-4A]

## P83C51FB-5A
designator U?
80C51 8-Bit Microcontroller Family: 256 B RAM, 16 kB ROM, 2.7V-5.5V, Low Power, High Speed
footprint SOT187-2_N (Leaded Chip Carrier, 44-Leads, Body 16.6x16.6mm, Pitch 1.27mm, IPC Medium Density)
footprint SOT187-2_L (Leaded Chip Carrier, 44-Leads, Body 16.6x16.6mm, Pitch 1.27mm, IPC High Density)
footprint SOT187-2_M (Leaded Chip Carrier, 44-Leads, Body 16.6x16.6mm, Pitch 1.27mm, IPC Low Density)
pins: 1 NIC, 2 P1.0/T2 (io), 3 P1.1/T2EX (io), 4 P1.2/ECI (io), 5 P1.3/CEX0 (io), 6 P1.4/CEX1 (io), 7 P1.5/CEX2 (io), 8 P1.6/CEX3 (io), 9 P1.7/CEX4 (io), 10 RST (in), 11 P3.0/RxD (io), 12 NIC, 13 P3.1/TxD (io), 14 P3.2/~{INT}0 (io), 15 P3.3/~{INT}1 (io), 16 P3.4/T0 (io), 17 P3.5/T1 (io), 18 P3.6/~{WR} (io), 19 P3.7/~{RD} (io), 20 XTAL2 (out), 21 XTAL1 (in), 22 VSS (power), 23 NIC, 24 P2.0/A8 (io), 25 P2.1/A9 (io), 26 P2.2/A10 (io), 27 P2.3/A11 (io), 28 P2.4/A12 (io), 29 P2.5/A13 (io), 30 P2.6/A14 (io), 31 P2.7/A15 (io), 32 ~{PSEN} (out), 33 ALE/~{PROG} (io), 34 NIC, 35 ~{EA}/VPP (in), 36 P0.7/AD7 (io), 37 P0.6/AD6 (io), 38 P0.5/AD5 (io), 39 P0.4/AD4 (io), 40 P0.3/AD3 (io), 41 P0.2/AD2 (io), 42 P0.1/AD1 (io), 43 P0.0/AD0 (io), 44 VCC (power)

## P83C51FB-5B
designator U?
80C51 8-Bit Microcontroller Family: 256 B RAM, 16 kB ROM, 2.7V-5.5V, Low Power, High Speed
footprint SOT307-2_N (QFP, 44-Leads, Body 10x10mm, Pitch 0.8mm, IPC Medium Density)
footprint SOT307-2_L (QFP, 44-Leads, Body 10x10mm, Pitch 0.8mm, IPC High Density)
footprint SOT307-2_M (QFP, 44-Leads, Body 10x10mm, Pitch 0.8mm, IPC Low Density)
pins: 1 P1.5/CEX2 (io), 2 P1.6/CEX3 (io), 3 P1.7/CEX4 (io), 4 RST (in), 5 P3.0/RxD (io), 6 NIC, 7 P3.1/TxD (io), 8 P3.2/~{INT}0 (io), 9 P3.3/~{INT}1 (io), 10 P3.4/T0 (io), 11 P3.5/T1 (io), 12 P3.6/~{WR} (io), 13 P3.7/~{RD} (io), 14 XTAL2 (out), 15 XTAL1 (in), 16 VSS (power), 17 NIC, 18 P2.0/A8 (io), 19 P2.1/A9 (io), 20 P2.2/A10 (io), 21 P2.3/A11 (io), 22 P2.4/A12 (io), 23 P2.5/A13 (io), 24 P2.6/A14 (io), 25 P2.7/A15 (io), 26 ~{PSEN} (out), 27 ALE/~{PROG} (io), 28 NIC, 29 ~{EA}/VPP (in), 30 P0.7/AD7 (io), 31 P0.6/AD6 (io), 32 P0.5/AD5 (io), 33 P0.4/AD4 (io), 34 P0.3/AD3 (io), 35 P0.2/AD2 (io), 36 P0.1/AD1 (io), 37 P0.0/AD0 (io), 38 VCC (power), 39 NIC, 40 P1.0/T2 (io), 41 P1.1/T2EX (io), 42 P1.2/ECI (io), 43 P1.3/CEX0 (io), 44 P1.4/CEX1 (io)

## P83C51FB-5N
designator U?
80C51 8-Bit Microcontroller Family: 256 B RAM, 16 kB ROM, 2.7V-5.5V, Low Power, High Speed
footprint SOT129-1 (DIP, Plastic; 40 Leads; Row Spacing 15.24 mm; Pitch 2.54 mm)
pins: 1 P1.0/T2 (io), 2 P1.1/T2EX (io), 3 P1.2/ECI (io), 4 P1.3/CEX0 (io), 5 P1.4/CEX1 (io), 6 P1.5/CEX2 (io), 7 P1.6/CEX3 (io), 8 P1.7/CEX4 (io), 9 RST (in), 10 P3.0/RxD (io), 11 P3.1/TxD (io), 12 P3.2/~{INT}0 (io), 13 P3.3/~{INT}1 (io), 14 P3.4/T0 (io), 15 P3.5/T1 (io), 16 P3.6/~{WR} (io), 17 P3.7/~{RD} (io), 18 XTAL2 (out), 19 XTAL1 (in), 20 VSS (power), 21 P2.0/A8 (io), 22 P2.1/A9 (io), 23 P2.2/A10 (io), 24 P2.3/A11 (io), 25 P2.4/A12 (io), 26 P2.5/A13 (io), 27 P2.6/A14 (io), 28 P2.7/A15 (io), 29 ~{PSEN} (out), 30 ALE/~{PROG} (io), 31 ~{EA}/VPP (in), 32 P0.7/AD7 (io), 33 P0.6/AD6 (io), 34 P0.5/AD5 (io), 35 P0.4/AD4 (io), 36 P0.3/AD3 (io), 37 P0.2/AD2 (io), 38 P0.1/AD1 (io), 39 P0.0/AD0 (io), 40 VCC (power)

## P83C51FB-IA
designator U?
80C51 8-Bit Microcontroller Family: 256 B RAM, 16 kB ROM, 5V, Low Power, High Speed
footprint SOT187-2_N (Leaded Chip Carrier, 44-Leads, Body 16.6x16.6mm, Pitch 1.27mm, IPC Medium Density)
footprint SOT187-2_L (Leaded Chip Carrier, 44-Leads, Body 16.6x16.6mm, Pitch 1.27mm, IPC High Density)
footprint SOT187-2_M (Leaded Chip Carrier, 44-Leads, Body 16.6x16.6mm, Pitch 1.27mm, IPC Low Density)
pins: 1 NIC, 2 P1.0/T2 (io), 3 P1.1/T2EX (io), 4 P1.2/ECI (io), 5 P1.3/CEX0 (io), 6 P1.4/CEX1 (io), 7 P1.5/CEX2 (io), 8 P1.6/CEX3 (io), 9 P1.7/CEX4 (io), 10 RST (in), 11 P3.0/RxD (io), 12 NIC, 13 P3.1/TxD (io), 14 P3.2/~{INT}0 (io), 15 P3.3/~{INT}1 (io), 16 P3.4/T0 (io), 17 P3.5/T1 (io), 18 P3.6/~{WR} (io), 19 P3.7/~{RD} (io), 20 XTAL2 (out), 21 XTAL1 (in), 22 VSS (power), 23 NIC, 24 P2.0/A8 (io), 25 P2.1/A9 (io), 26 P2.2/A10 (io), 27 P2.3/A11 (io), 28 P2.4/A12 (io), 29 P2.5/A13 (io), 30 P2.6/A14 (io), 31 P2.7/A15 (io), 32 ~{PSEN} (out), 33 ALE/~{PROG} (io), 34 NIC, 35 ~{EA}/VPP (in), 36 P0.7/AD7 (io), 37 P0.6/AD6 (io), 38 P0.5/AD5 (io), 39 P0.4/AD4 (io), 40 P0.3/AD3 (io), 41 P0.2/AD2 (io), 42 P0.1/AD1 (io), 43 P0.0/AD0 (io), 44 VCC (power)

## P83C51FB-IB
designator U?
80C51 8-Bit Microcontroller Family: 256 B RAM, 16 kB ROM, 5V, Low Power, High Speed
footprint SOT307-2_N (QFP, 44-Leads, Body 10x10mm, Pitch 0.8mm, IPC Medium Density)
footprint SOT307-2_L (QFP, 44-Leads, Body 10x10mm, Pitch 0.8mm, IPC High Density)
footprint SOT307-2_M (QFP, 44-Leads, Body 10x10mm, Pitch 0.8mm, IPC Low Density)
pins: 1 P1.5/CEX2 (io), 2 P1.6/CEX3 (io), 3 P1.7/CEX4 (io), 4 RST (in), 5 P3.0/RxD (io), 6 NIC, 7 P3.1/TxD (io), 8 P3.2/~{INT}0 (io), 9 P3.3/~{INT}1 (io), 10 P3.4/T0 (io), 11 P3.5/T1 (io), 12 P3.6/~{WR} (io), 13 P3.7/~{RD} (io), 14 XTAL2 (out), 15 XTAL1 (in), 16 VSS (power), 17 NIC, 18 P2.0/A8 (io), 19 P2.1/A9 (io), 20 P2.2/A10 (io), 21 P2.3/A11 (io), 22 P2.4/A12 (io), 23 P2.5/A13 (io), 24 P2.6/A14 (io), 25 P2.7/A15 (io), 26 ~{PSEN} (out), 27 ALE/~{PROG} (io), 28 NIC, 29 ~{EA}/VPP (in), 30 P0.7/AD7 (io), 31 P0.6/AD6 (io), 32 P0.5/AD5 (io), 33 P0.4/AD4 (io), 34 P0.3/AD3 (io), 35 P0.2/AD2 (io), 36 P0.1/AD1 (io), 37 P0.0/AD0 (io), 38 VCC (power), 39 NIC, 40 P1.0/T2 (io), 41 P1.1/T2EX (io), 42 P1.2/ECI (io), 43 P1.3/CEX0 (io), 44 P1.4/CEX1 (io)

## P83C51FB-IN
designator U?
80C51 8-Bit Microcontroller Family: 256 B RAM, 16 kB ROM, 5V, Low Power, High Speed
footprint SOT129-1 (DIP, Plastic; 40 Leads; Row Spacing 15.24 mm; Pitch 2.54 mm)
pins: 1 P1.0/T2 (io), 2 P1.1/T2EX (io), 3 P1.2/ECI (io), 4 P1.3/CEX0 (io), 5 P1.4/CEX1 (io), 6 P1.5/CEX2 (io), 7 P1.6/CEX3 (io), 8 P1.7/CEX4 (io), 9 RST (in), 10 P3.0/RxD (io), 11 P3.1/TxD (io), 12 P3.2/~{INT}0 (io), 13 P3.3/~{INT}1 (io), 14 P3.4/T0 (io), 15 P3.5/T1 (io), 16 P3.6/~{WR} (io), 17 P3.7/~{RD} (io), 18 XTAL2 (out), 19 XTAL1 (in), 20 VSS (power), 21 P2.0/A8 (io), 22 P2.1/A9 (io), 23 P2.2/A10 (io), 24 P2.3/A11 (io), 25 P2.4/A12 (io), 26 P2.5/A13 (io), 27 P2.6/A14 (io), 28 P2.7/A15 (io), 29 ~{PSEN} (out), 30 ALE/~{PROG} (io), 31 ~{EA}/VPP (in), 32 P0.7/AD7 (io), 33 P0.6/AD6 (io), 34 P0.5/AD5 (io), 35 P0.4/AD4 (io), 36 P0.3/AD3 (io), 37 P0.2/AD2 (io), 38 P0.1/AD1 (io), 39 P0.0/AD0 (io), 40 VCC (power)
